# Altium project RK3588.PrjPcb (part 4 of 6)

## Sheet EMMC.SchDoc
size B; SheetNumber: 11; SheetTotal: 22
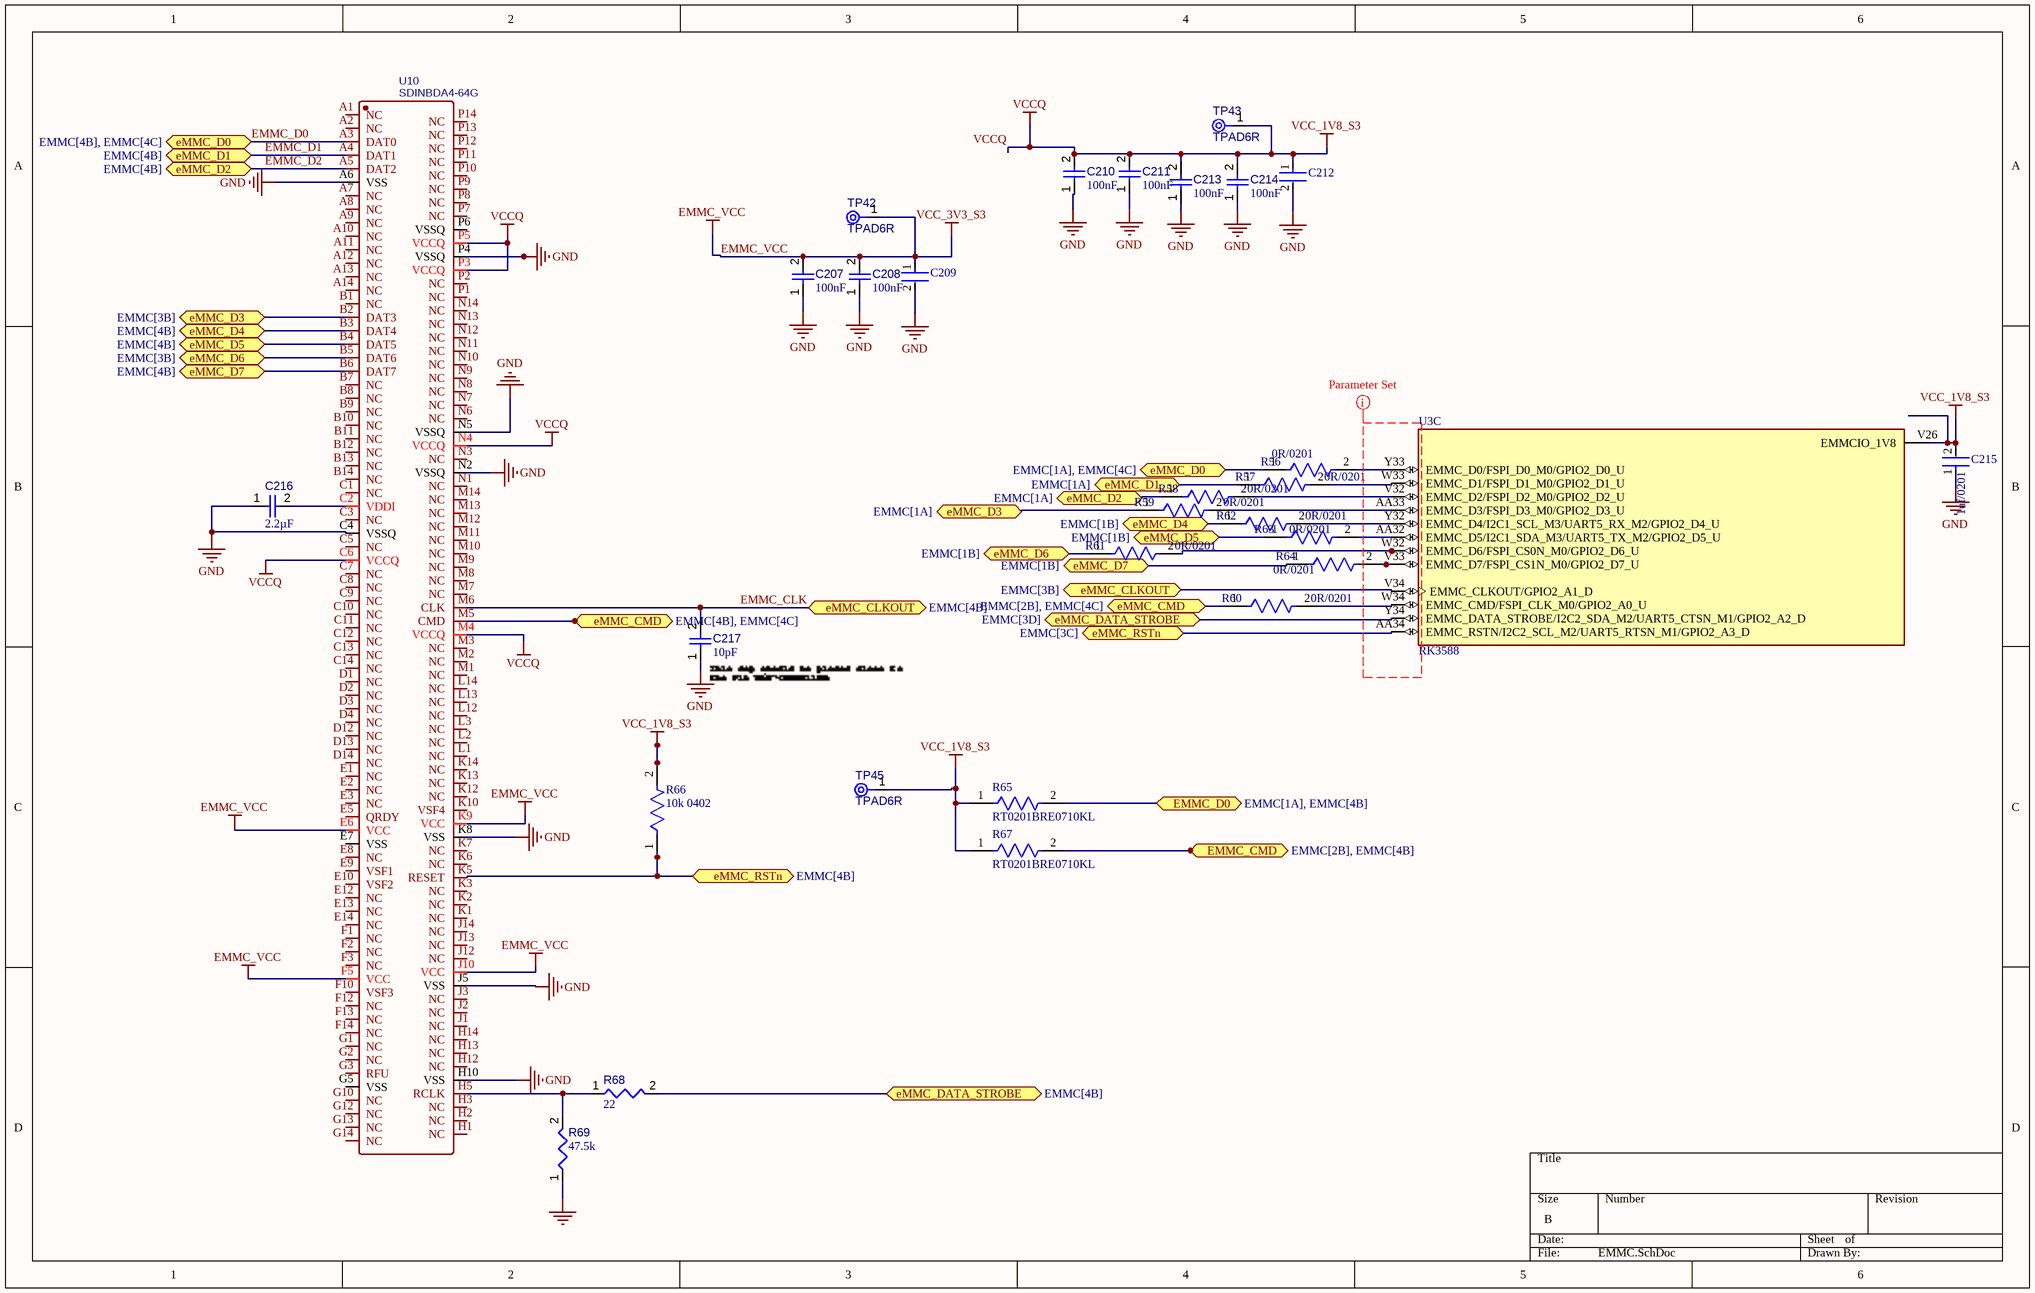
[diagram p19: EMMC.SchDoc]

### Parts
C207  value 100nF  [CAPC1005X56X25LL10T15]  (hidden comment: Capacitor 0.1 uF +/- 5% 16 V 0402)
C208  value 100nF  [CAPC1005X56X25LL10T15]  (hidden comment: Capacitor 0.1 uF +/- 5% 16 V 0402)
C209  CC0402MRX5R7BB475  [FP-CC0402-MFG]  (value not drawn)
C210  value 100nF  [CAPC1005X56X25LL10T15]  (hidden comment: Capacitor 0.1 uF +/- 5% 16 V 0402)
C211  value 100nF  [CAPC1005X56X25LL10T15]  (hidden comment: Capacitor 0.1 uF +/- 5% 16 V 0402)
C212  CC0402MRX5R7BB475  [FP-CC0402-MFG]  (value not drawn)
C213  value 100nF  [CAPC1005X56X25LL10T15]  (hidden comment: Capacitor 0.1 uF +/- 5% 16 V 0402)
C214  value 100nF  [CAPC1005X56X25LL10T15]  (hidden comment: Capacitor 0.1 uF +/- 5% 16 V 0402)
C215  1uf/0201  [FP-CC0201-BA-MFG]
C216  value 2.2µF  [CAPC0402(1005)60_L]  (hidden comment: Capacitor 2,2µF +/-20% 10V 0402)
C217  value 10pF  [CAPC1005X55X30LL05T10]  (hidden comment: Capacitor 10 pF +/- 0.25 pF 50 V 0402)
R56  0R/0201  [FP-RMCF0201-IPC_C]
R57  0R/0201  [FP-RMCF0201-IPC_C]
R58  0R/0201  [FP-RMCF0201-IPC_C]
R59  0R/0201  [FP-RMCF0201-IPC_C]
R60  0R/0201  [FP-RMCF0201-IPC_C]
R61  0R/0201  [FP-RMCF0201-IPC_C]
R62  0R/0201  [FP-RMCF0201-IPC_C]
R63  0R/0201  [FP-RMCF0201-IPC_C]
R64  0R/0201  [FP-RMCF0201-IPC_C]
R65  RT0201BRE0710KL  [FP-RT0201-MFG]
R66  10k 0402  [FP-CRGCQ0402-IPC_C]
R67  RT0201BRE0710KL  [FP-RT0201-MFG]
R68  value 22  [RESC0402(1005)_L]  (hidden comment: 22R2J)
R69  value 47.5k  [RESC0402(1005)_L]  (hidden comment: 47D5KR2F)
TP42  TPAD6R  [TP06R]  (no BOM)
TP43  TPAD6R  [TP06R]  (no BOM)
TP45  TPAD6R  [TP06R]  (no BOM)
U3  RK3588  [BGA1088C65P34X34_2300X2300X204N]  (part C of 30)
U10  SDINBDA4-64G  [FBGA-153_L13.0-W11.5-P0.50_KLMAG1JETD-B041]

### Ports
eMMC_CLKOUT (bidir, see EMMC[3B]), eMMC_CLKOUT (bidir, see EMMC[4B]), EMMC_CMD (bidir, see EMMC[2B], EMMC[4B]), eMMC_CMD (bidir, see EMMC[2B], EMMC[4C]), eMMC_CMD (bidir, see EMMC[4B], EMMC[4C]), EMMC_D0 (bidir, see EMMC[1A], EMMC[4B]), eMMC_D0 (bidir, see EMMC[1A], EMMC[4C]), eMMC_D0 (bidir, see EMMC[4B], EMMC[4C]), eMMC_D1 (bidir, see EMMC[1A]), eMMC_D1 (bidir, see EMMC[4B]), eMMC_D2 (bidir, see EMMC[1A]), eMMC_D2 (bidir, see EMMC[4B]), eMMC_D3 (bidir, see EMMC[1A]), eMMC_D3 (bidir, see EMMC[3B]), eMMC_D4 (bidir, see EMMC[1B]), eMMC_D4 (bidir, see EMMC[4B]), eMMC_D5 (bidir, see EMMC[1B]), eMMC_D5 (bidir, see EMMC[4B]), eMMC_D6 (bidir, see EMMC[1B]), eMMC_D6 (bidir, see EMMC[3B]), eMMC_D7 (bidir, see EMMC[1B]), eMMC_D7 (bidir, see EMMC[4B]), eMMC_DATA_STROBE (bidir, see EMMC[3D]), eMMC_DATA_STROBE (bidir, see EMMC[4B]), eMMC_RSTn (bidir, see EMMC[3C]), eMMC_RSTn (bidir, see EMMC[4B])

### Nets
EMMC_VCC: C207.2 C208.2 C209.1 TP42.1(TP) U10.E6(VCC) U10.F5(VCC) U10.J10(VCC) U10.K9(VCC)  [also labelled VCC_3V3_S3]
GND: C207.1 C208.1 C209.2 C210.1 C211.1 C212.2 C213.1 C214.1 C215.1 C216.1 C217.1 R69.1 U10.A6(VSS) U10.C4(VSSQ) U10.H10(VSS) U10.J5(VSS) U10.K8(VSS) U10.N2(VSSQ) U10.N5(VSSQ) U10.P4(VSSQ)
VCCQ: C210.2 C211.2 C212.1 C213.2 C214.2 C215.2 R65.1 R66.2 R67.1 TP43.1(TP) TP45.1(TP) U3.V26(EMMCIO_1V8) U10.C6(VCCQ) U10.M4(VCCQ) U10.N4(VCCQ) U10.P3(VCCQ) U10.P5(VCCQ)  [also labelled VCC_1V8_S3]
EMMC_CLK: C217.2 U3.V34(EMMC_CLKOUT/GPIO2_A1_D) U10.M6(CLK) ; port eMMC_CLKOUT
eMMC_CMD: R60.1 R67.2 U10.M5(CMD) ; port eMMC_CMD, port EMMC_CMD
EMMC_D0: R56.1 R65.2 U10.A3(DAT0) ; port eMMC_D0, port EMMC_D0
EMMC_D1: R57.1 U10.A4(DAT1) ; port eMMC_D1
EMMC_D2: R58.1 U10.A5(DAT2) ; port eMMC_D2
eMMC_D3: R59.1 U10.B2(DAT3) ; port eMMC_D3
eMMC_D4: R62.1 U10.B3(DAT4) ; port eMMC_D4
eMMC_D5: R63.1 U10.B4(DAT5) ; port eMMC_D5
eMMC_D6: R61.1 U10.B5(DAT6) ; port eMMC_D6
eMMC_D7: R64.1 U10.B6(DAT7) ; port eMMC_D7
eMMC_DATA_STROBE: R68.2 U3.Y34(EMMC_DATA_STROBE/I2C2_SDA_M2/UART5_CTSN_M1/GPIO2_A2_D) ; port eMMC_DATA_STROBE
eMMC_RSTn: R66.1 U3.AA34(EMMC_RSTN/I2C2_SCL_M2/UART5_RTSN_M1/GPIO2_A3_D) U10.K5(RESET) ; port eMMC_RSTn
NetC216_2: C216.2 U10.C2(VDDI)
NetR56_2: R56.2 U3.Y33(EMMC_D0/FSPI_D0_M0/GPIO2_D0_U)
NetR57_2: R57.2 U3.W33(EMMC_D1/FSPI_D1_M0/GPIO2_D1_U)
NetR58_2: R58.2 U3.V32(EMMC_D2/FSPI_D2_M0/GPIO2_D2_U)
NetR59_2: R59.2 U3.AA33(EMMC_D3/FSPI_D3_M0/GPIO2_D3_U)
NetR60_2: R60.2 U3.W34(EMMC_CMD/FSPI_CLK_M0/GPIO2_A0_U)
NetR61_2: R61.2 U3.W32(EMMC_D6/FSPI_CS0N_M0/GPIO2_D6_U)
NetR62_2: R62.2 U3.Y32(EMMC_D4/I2C1_SCL_M3/UART5_RX_M2/GPIO2_D4_U)
NetR63_2: R63.2 U3.AA32(EMMC_D5/I2C1_SDA_M3/UART5_TX_M2/GPIO2_D5_U)
NetR64_2: R64.2 U3.V33(EMMC_D7/FSPI_CS1N_M0/GPIO2_D7_U)
NetR68_1: R68.1 R69.2 U10.H5(RCLK)

Not connected (* = marked no-connect by the designer): U10 A1(NC) A2(NC) A7(NC) A8(NC) A9(NC) A10(NC) A11(NC) A12(NC) A13(NC) A14(NC) B1(NC) B7(NC) B8(NC) B9(NC) B10(NC) B11(NC) B12(NC) B13(NC) B14(NC) C1(NC) C3(NC) C5(NC) C7(NC) C8(NC) C9(NC) C10(NC) C11(NC) C12(NC) C13(NC) C14(NC) D1(NC) D2(NC) D3(NC) D4(NC) D12(NC) D13(NC) D14(NC) E1(NC) E2(NC) E3(NC) E5(QRDY) E7(VSS) E8(NC) E9(VSF1) E10(VSF2) E12(NC) E13(NC) E14(NC) F1(NC) F2(NC) F3(NC) F10(VSF3) F12(NC) F13(NC) F14(NC) G1(NC) G2(NC) G3(RFU) G5(VSS) G10(NC) G12(NC) G13(NC) G14(NC) H1(NC) H2(NC) H3(NC) H12(NC) H13(NC) H14(NC) J1(NC) J2(NC) J3(NC) J12(NC) J13(NC) J14(NC) K1(NC) K2(NC) K3(NC) K6(NC) K7(NC) K10(VSF4) K12(NC) K13(NC) K14(NC) L1(NC) L2(NC) L3(NC) L12(NC) L13(NC) L14(NC) M1(NC) M2(NC) M3(NC) M7(NC) M8(NC) M9(NC) M10(NC) M11(NC) M12(NC) M13(NC) M14(NC) N1(NC) N3(NC) N6(NC) N7(NC) N8(NC) N9(NC) N10(NC) N11(NC) N12(NC) N13(NC) N14(NC) P1(NC) P2(NC) P6(VSSQ) P7(NC) P8(NC) P9(NC) P10(NC) P11(NC) P12(NC) P13(NC) P14(NC)

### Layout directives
net class EMMC_50: (no net found under the mark)

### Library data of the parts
C207 C208 C210 C211 C213 C214 = CMP-001-00001-6: Chip Capacitor, 0.1 uF, +/- 5%, 16 V, 0402 (1005 Metric); Capacitor Type: Ceramic; Voltage Rating: 16V
C209 C212 = CMP-03422-000819-1: CAP CER 4.7UF 16V X5R 0402; Manufacturer: YAGEO; Tolerance: 0.2; Automotive Grade: NA; Material: Ceramic; Temperature Coefficient: 30ppm/°C
C215 = CMP-03422-000660-2: 1uF 6.3V X5R ±20% 0201 Multilayer Ceramic Capacitors MLCC - SMD/SMT ROHS; Manufacturer: Yageo; Manufacturer Part Number: CC0201MRX5R5BB105; Tolerance: 0.2; Temperature Coefficient: 15%; MN: CL03A105MQ3CSNH
C216 = CMP-001-00056-4: Chip Capacitor, 2,2µF +/-20%, 10V, 0402, Thickness 0.6 mm; Tolerance: 10%
C217 = CMP-001-00011-6: Chip Capacitor, 10 pF, +/- 0.25 pF, 50 V, 0402 (1005 Metric); Voltage Rating: 50V; Tolerance: 0.25%; Capacitor Type: Ceramic
R56-R64 = CMP-26527-001890-1: -55℃~+155℃ 0Ω 25V 50mW Thick Film Resistor 0201 Chip Resistor - Surface Mount ROHS; Resistance: 0R; MN: RMCF0201ZT0R00
R65 R67 = CMP-03412-006200-1: RT0201 10KΩ 0.05W 50 ppm/°C 0.10%; Manufacturer: Yageo; Voltage Rating: 25V; Tolerance: 0.001
R66 = CMP-03211-008081-1: CRGCQ 0402 10K 5%; Manufacturer: TE Connectivity; Manufacturer Part Number: CRGCQ0402J10K; Power Rating: 0.0625W; Tolerance: 0.05; Voltage Rating: 50V; Temperature Coefficient: ±100ppm/°C; Resistance: 10KΩ; Value: 10KΩ
R68 = CMP-009-00082-2: 22R 0.063W 5% 0402 (1005 Metric)  SMD; Power: 63mW
R69 = CMP-009-00103-2: 47K5 0.063W 1% 0402 (1005 Metric)  SMD; Power: 63mW
TP42 TP43 TP45 = CMP-00028-00002-2: 0.6mm round
U3 = RK3588: low power, high performance processor; MF: Fuzhou Rockchip Electronics Co
U10 = SDINBDA4-64G: Manufacturer: SANDISK(闪迪); Contributor: LCSC

## Sheet LPDDR4_EDA.SchDoc
size C; SheetNumber: 12; SheetTotal: 22
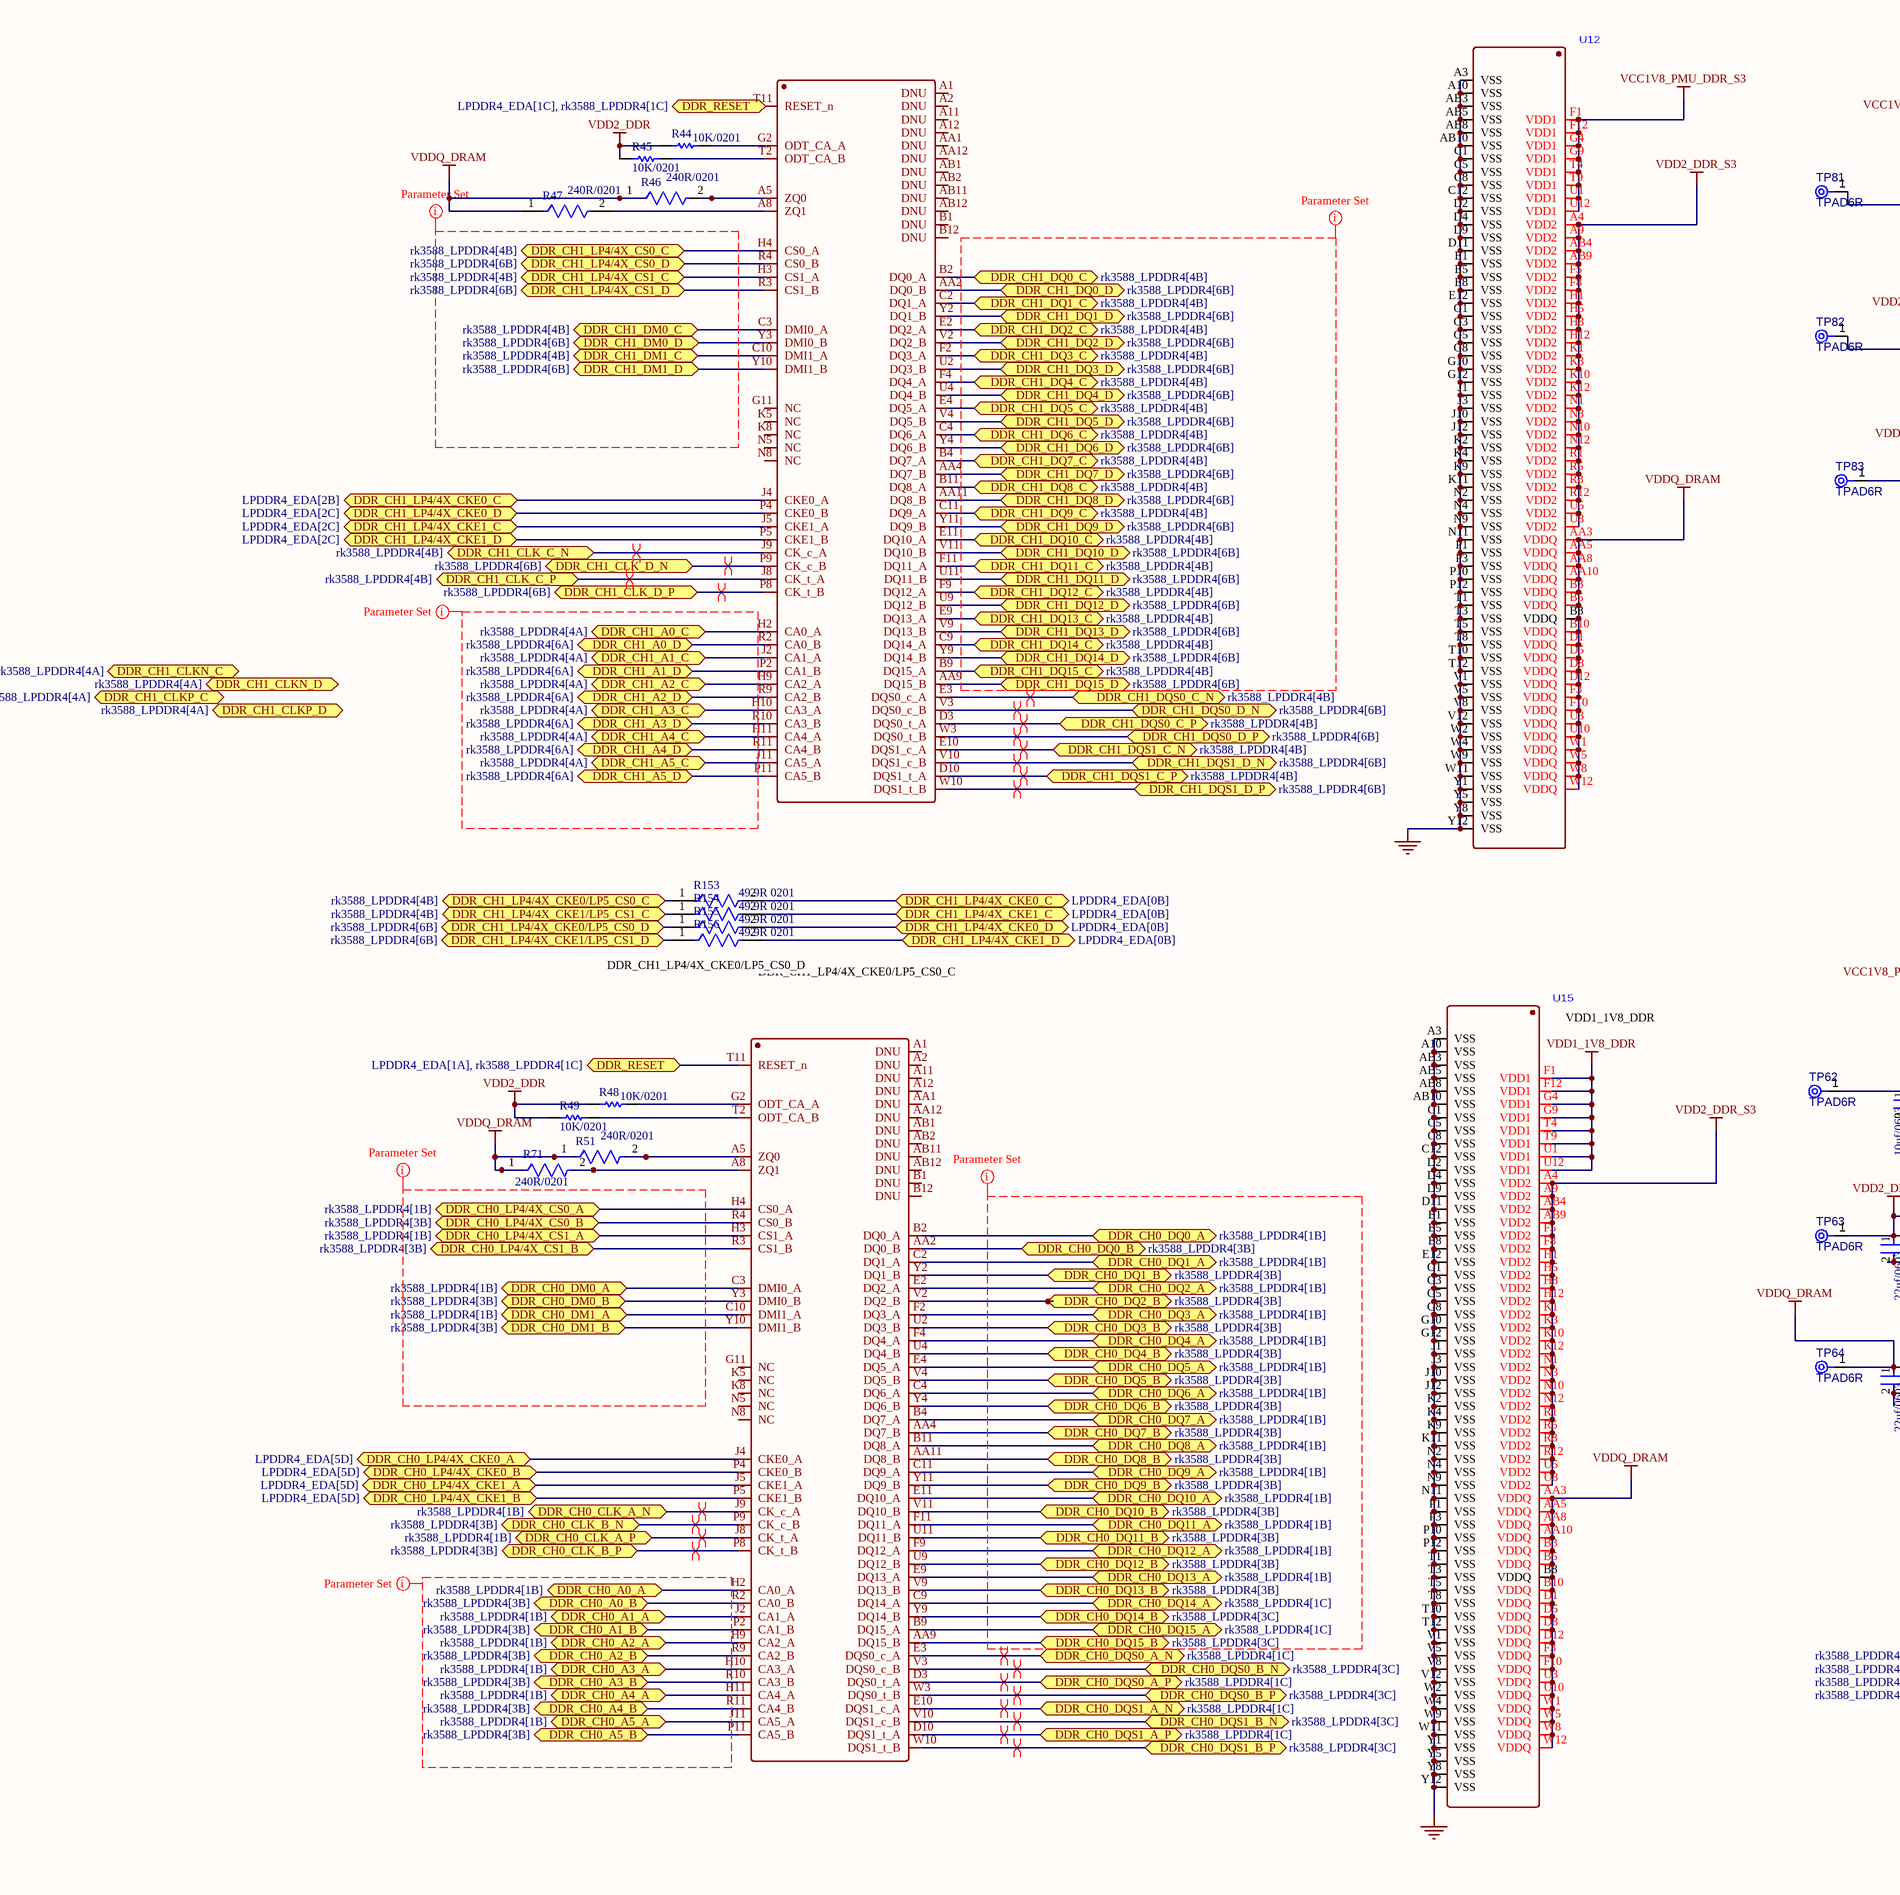
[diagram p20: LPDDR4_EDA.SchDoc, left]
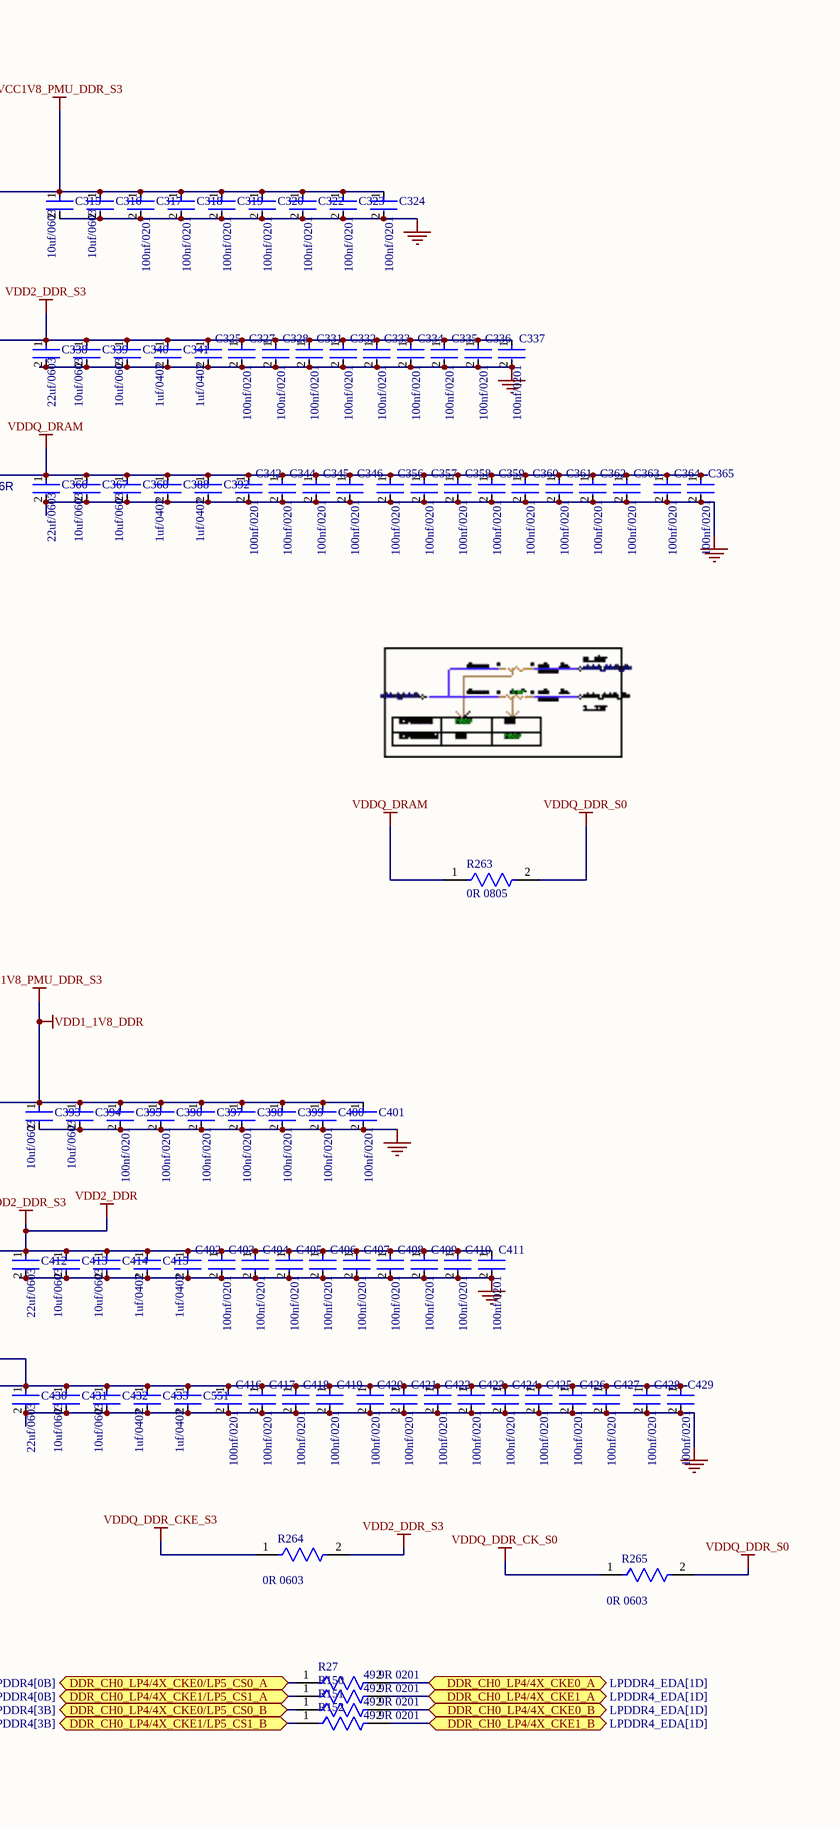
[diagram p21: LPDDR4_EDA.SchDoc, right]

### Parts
C315  10uf/0603  [FP-CC0603-DC-MFG]
C316  10uf/0603  [FP-CC0603-DC-MFG]
C317  100nf/0201  [FP-CC0201-BA-MFG]
C318  100nf/0201  [FP-CC0201-BA-MFG]
C319  100nf/0201  [FP-CC0201-BA-MFG]
C320  100nf/0201  [FP-CC0201-BA-MFG]
C322  100nf/0201  [FP-CC0201-BA-MFG]
C323  100nf/0201  [FP-CC0201-BA-MFG]
C324  100nf/0201  [FP-CC0201-BA-MFG]
C325  1uf/0402  [FP-C0402C105K8PACTU-MFG]
C327  100nf/0201  [FP-CC0201-BA-MFG]
C328  100nf/0201  [FP-CC0201-BA-MFG]
C331  100nf/0201  [FP-CC0201-BA-MFG]
C332  100nf/0201  [FP-CC0201-BA-MFG]
C333  100nf/0201  [FP-CC0201-BA-MFG]
C334  100nf/0201  [FP-CC0201-BA-MFG]
C335  100nf/0201  [FP-CC0201-BA-MFG]
C336  100nf/0201  [FP-CC0201-BA-MFG]
C337  100nf/0201  [FP-CC0201-BA-MFG]
C338  22uf/0603  [FP-GRM186-0_2-MFG]
C339  10uf/0603  [FP-CC0603-DC-MFG]
C340  10uf/0603  [FP-CC0603-DC-MFG]
C341  1uf/0402  [FP-C0402C105K8PACTU-MFG]
C342  100nf/0201  [FP-CC0201-BA-MFG]
C344  100nf/0201  [FP-CC0201-BA-MFG]
C345  100nf/0201  [FP-CC0201-BA-MFG]
C346  100nf/0201  [FP-CC0201-BA-MFG]
C356  100nf/0201  [FP-CC0201-BA-MFG]
C357  100nf/0201  [FP-CC0201-BA-MFG]
C358  100nf/0201  [FP-CC0201-BA-MFG]
C359  100nf/0201  [FP-CC0201-BA-MFG]
C360  100nf/0201  [FP-CC0201-BA-MFG]
C361  100nf/0201  [FP-CC0201-BA-MFG]
C362  100nf/0201  [FP-CC0201-BA-MFG]
C363  100nf/0201  [FP-CC0201-BA-MFG]
C364  100nf/0201  [FP-CC0201-BA-MFG]
C365  100nf/0201  [FP-CC0201-BA-MFG]
C366  22uf/0603  [FP-GRM186-0_2-MFG]
C367  10uf/0603  [FP-CC0603-DC-MFG]
C368  10uf/0603  [FP-CC0603-DC-MFG]
C388  1uf/0402  [FP-C0402C105K8PACTU-MFG]
C392  1uf/0402  [FP-C0402C105K8PACTU-MFG]
C393  10uf/0603  [FP-CC0603-DC-MFG]
C394  10uf/0603  [FP-CC0603-DC-MFG]
C395  100nf/0201  [FP-CC0201-BA-MFG]
C396  100nf/0201  [FP-CC0201-BA-MFG]
C397  100nf/0201  [FP-CC0201-BA-MFG]
C398  100nf/0201  [FP-CC0201-BA-MFG]
C399  100nf/0201  [FP-CC0201-BA-MFG]
C400  100nf/0201  [FP-CC0201-BA-MFG]
C401  100nf/0201  [FP-CC0201-BA-MFG]
C402  1uf/0402  [FP-C0402C105K8PACTU-MFG]
C403  100nf/0201  [FP-CC0201-BA-MFG]
C404  100nf/0201  [FP-CC0201-BA-MFG]
C405  100nf/0201  [FP-CC0201-BA-MFG]
C406  100nf/0201  [FP-CC0201-BA-MFG]
C407  100nf/0201  [FP-CC0201-BA-MFG]
C408  100nf/0201  [FP-CC0201-BA-MFG]
C409  100nf/0201  [FP-CC0201-BA-MFG]
C410  100nf/0201  [FP-CC0201-BA-MFG]
C411  100nf/0201  [FP-CC0201-BA-MFG]
C412  22uf/0603  [FP-GRM186-0_2-MFG]
C413  10uf/0603  [FP-CC0603-DC-MFG]
C414  10uf/0603  [FP-CC0603-DC-MFG]
C415  1uf/0402  [FP-C0402C105K8PACTU-MFG]
C416  100nf/0201  [FP-CC0201-BA-MFG]
C417  100nf/0201  [FP-CC0201-BA-MFG]
C418  100nf/0201  [FP-CC0201-BA-MFG]
C419  100nf/0201  [FP-CC0201-BA-MFG]
C420  100nf/0201  [FP-CC0201-BA-MFG]
C421  100nf/0201  [FP-CC0201-BA-MFG]
C422  100nf/0201  [FP-CC0201-BA-MFG]
C423  100nf/0201  [FP-CC0201-BA-MFG]
C424  100nf/0201  [FP-CC0201-BA-MFG]
C425  100nf/0201  [FP-CC0201-BA-MFG]
C426  100nf/0201  [FP-CC0201-BA-MFG]
C427  100nf/0201  [FP-CC0201-BA-MFG]
C428  100nf/0201  [FP-CC0201-BA-MFG]
C429  100nf/0201  [FP-CC0201-BA-MFG]
C430  22uf/0603  [FP-GRM186-0_2-MFG]
C431  10uf/0603  [FP-CC0603-DC-MFG]
C432  10uf/0603  [FP-CC0603-DC-MFG]
C433  1uf/0402  [FP-C0402C105K8PACTU-MFG]
C551  1uf/0402  [FP-C0402C105K8PACTU-MFG]
R27  49.9R 0201  [FP-AF0201-MFG]
R44  10K/0201  [RESC0603X28X15LL05T05]
R45  10K/0201  [RESC0603X28X15LL05T05]
R46  240R/0201  [FP-RMCF0201-IPC_C]
R47  240R/0201  [FP-RMCF0201-IPC_C]
R48  10K/0201  [RESC0603X28X15LL05T05]
R49  10K/0201  [RESC0603X28X15LL05T05]
R51  240R/0201  [FP-RMCF0201-IPC_C]
R71  240R/0201  [FP-RMCF0201-IPC_C]
R150  49.9R 0201  [FP-AF0201-MFG]
R151  49.9R 0201  [FP-AF0201-MFG]
R152  49.9R 0201  [FP-AF0201-MFG]
R153  49.9R 0201  [FP-AF0201-MFG]
R154  49.9R 0201  [FP-AF0201-MFG]
R155  49.9R 0201  [FP-AF0201-MFG]
R156  49.9R 0201  [FP-AF0201-MFG]
R263  0R 0805  [FP-AF0805-IPC_B]
R264  0R 0603  [FP-AC0603-IPC_C]
R265  0R 0603  [FP-AC0603-IPC_C]
TP62  TPAD6R  [TP06R]  (no BOM)
TP63  TPAD6R  [TP06R]  (no BOM)
TP64  TPAD6R  [TP06R]  (no BOM)
TP81  TPAD6R  [TP06R]  (no BOM)
TP82  TPAD6R  [TP06R]  (no BOM)
TP83  TPAD6R  [TP06R]  (no BOM)
U12  (no value)  [WFBGA-200_L14.5-W10.0-BL_MT53D512M32D2DS]
U15  (no value)  [WFBGA-200_L14.5-W10.0-BL_MT53D512M32D2DS]

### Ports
DDR_CH0_A0_A (bidir, see rk3588_LPDDR4[1B]), DDR_CH0_A0_B (bidir, see rk3588_LPDDR4[3B]), DDR_CH0_A1_A (bidir, see rk3588_LPDDR4[1B]), DDR_CH0_A1_B (bidir, see rk3588_LPDDR4[3B]), DDR_CH0_A2_A (bidir, see rk3588_LPDDR4[1B]), DDR_CH0_A2_B (bidir, see rk3588_LPDDR4[3B]), DDR_CH0_A3_A (bidir, see rk3588_LPDDR4[1B]), DDR_CH0_A3_B (bidir, see rk3588_LPDDR4[3B]), DDR_CH0_A4_A (bidir, see rk3588_LPDDR4[1B]), DDR_CH0_A4_B (bidir, see rk3588_LPDDR4[3B]), DDR_CH0_A5_A (bidir, see rk3588_LPDDR4[1B]), DDR_CH0_A5_B (bidir, see rk3588_LPDDR4[3B]), DDR_CH0_CLK_A_N (bidir, see rk3588_LPDDR4[1B]), DDR_CH0_CLK_A_P (bidir, see rk3588_LPDDR4[1B]), DDR_CH0_CLK_B_N (bidir, see rk3588_LPDDR4[3B]), DDR_CH0_CLK_B_P (bidir, see rk3588_LPDDR4[3B]), DDR_CH0_DM0_A (bidir, see rk3588_LPDDR4[1B]), DDR_CH0_DM0_B (bidir, see rk3588_LPDDR4[3B]), DDR_CH0_DM1_A (bidir, see rk3588_LPDDR4[1B]), DDR_CH0_DM1_B (bidir, see rk3588_LPDDR4[3B]), DDR_CH0_DQ0_A (bidir, see rk3588_LPDDR4[1B]), DDR_CH0_DQ0_B (bidir, see rk3588_LPDDR4[3B]), DDR_CH0_DQ1_A (bidir, see rk3588_LPDDR4[1B]), DDR_CH0_DQ1_B (bidir, see rk3588_LPDDR4[3B]), DDR_CH0_DQ2_A (bidir, see rk3588_LPDDR4[1B]), DDR_CH0_DQ2_B (bidir, see rk3588_LPDDR4[3B]), DDR_CH0_DQ3_A (bidir, see rk3588_LPDDR4[1B]), DDR_CH0_DQ3_B (bidir, see rk3588_LPDDR4[3B]), DDR_CH0_DQ4_A (bidir, see rk3588_LPDDR4[1B]), DDR_CH0_DQ4_B (bidir, see rk3588_LPDDR4[3B]), DDR_CH0_DQ5_A (bidir, see rk3588_LPDDR4[1B]), DDR_CH0_DQ5_B (bidir, see rk3588_LPDDR4[3B]), DDR_CH0_DQ6_A (bidir, see rk3588_LPDDR4[1B]), DDR_CH0_DQ6_B (bidir, see rk3588_LPDDR4[3B]), DDR_CH0_DQ7_A (bidir, see rk3588_LPDDR4[1B]), DDR_CH0_DQ7_B (bidir, see rk3588_LPDDR4[3B]), DDR_CH0_DQ8_A (bidir, see rk3588_LPDDR4[1B]), DDR_CH0_DQ8_B (bidir, see rk3588_LPDDR4[3B]), DDR_CH0_DQ9_A (bidir, see rk3588_LPDDR4[1B]), DDR_CH0_DQ9_B (bidir, see rk3588_LPDDR4[3B]), DDR_CH0_DQ10_A (bidir, see rk3588_LPDDR4[1B]), DDR_CH0_DQ10_B (bidir, see rk3588_LPDDR4[3B]), DDR_CH0_DQ11_A (bidir, see rk3588_LPDDR4[1B]), DDR_CH0_DQ11_B (bidir, see rk3588_LPDDR4[3B]), DDR_CH0_DQ12_A (bidir, see rk3588_LPDDR4[1B]), DDR_CH0_DQ12_B (bidir, see rk3588_LPDDR4[3B]), DDR_CH0_DQ13_A (bidir, see rk3588_LPDDR4[1B]), DDR_CH0_DQ13_B (bidir, see rk3588_LPDDR4[3B]), DDR_CH0_DQ14_A (bidir, see rk3588_LPDDR4[1C]), DDR_CH0_DQ14_B (bidir, see rk3588_LPDDR4[3C]), DDR_CH0_DQ15_A (bidir, see rk3588_LPDDR4[1C]), DDR_CH0_DQ15_B (bidir, see rk3588_LPDDR4[3C]), DDR_CH0_DQS0_A_N (bidir, see rk3588_LPDDR4[1C]), DDR_CH0_DQS0_A_P (bidir, see rk3588_LPDDR4[1C]), DDR_CH0_DQS0_B_N (bidir, see rk3588_LPDDR4[3C]), DDR_CH0_DQS0_B_P (bidir, see rk3588_LPDDR4[3C]), DDR_CH0_DQS1_A_N (bidir, see rk3588_LPDDR4[1C]), DDR_CH0_DQS1_A_P (bidir, see rk3588_LPDDR4[1C]), DDR_CH0_DQS1_B_N (bidir, see rk3588_LPDDR4[3C]), DDR_CH0_DQS1_B_P (bidir, see rk3588_LPDDR4[3C]), DDR_CH0_LP4/4X_CKE0/LP5_CS0_A (bidir, see rk3588_LPDDR4[0B]), DDR_CH0_LP4/4X_CKE0/LP5_CS0_B (bidir, see rk3588_LPDDR4[3B]), DDR_CH0_LP4/4X_CKE0_A (bidir, see LPDDR4_EDA[1D]), DDR_CH0_LP4/4X_CKE0_A (bidir, see LPDDR4_EDA[5D]), DDR_CH0_LP4/4X_CKE0_B (bidir, see LPDDR4_EDA[1D]), DDR_CH0_LP4/4X_CKE0_B (bidir, see LPDDR4_EDA[5D]), DDR_CH0_LP4/4X_CKE1/LP5_CS1_A (bidir, see rk3588_LPDDR4[0B]), DDR_CH0_LP4/4X_CKE1/LP5_CS1_B (bidir, see rk3588_LPDDR4[3B]), DDR_CH0_LP4/4X_CKE1_A (bidir, see LPDDR4_EDA[1D]), DDR_CH0_LP4/4X_CKE1_A (bidir, see LPDDR4_EDA[5D]), DDR_CH0_LP4/4X_CKE1_B (bidir, see LPDDR4_EDA[1D]), DDR_CH0_LP4/4X_CKE1_B (bidir, see LPDDR4_EDA[5D]), DDR_CH0_LP4/4X_CS0_A (bidir, see rk3588_LPDDR4[1B]), DDR_CH0_LP4/4X_CS0_B (bidir, see rk3588_LPDDR4[3B]), DDR_CH0_LP4/4X_CS1_A (bidir, see rk3588_LPDDR4[1B]), DDR_CH0_LP4/4X_CS1_B (bidir, see rk3588_LPDDR4[3B]), DDR_CH1_A0_C (bidir, see rk3588_LPDDR4[4A]), DDR_CH1_A0_D (bidir, see rk3588_LPDDR4[6A]), DDR_CH1_A1_C (bidir, see rk3588_LPDDR4[4A]), DDR_CH1_A1_D (bidir, see rk3588_LPDDR4[6A]), DDR_CH1_A2_C (bidir, see rk3588_LPDDR4[4A]), DDR_CH1_A2_D (bidir, see rk3588_LPDDR4[6A]), DDR_CH1_A3_C (bidir, see rk3588_LPDDR4[4A]), DDR_CH1_A3_D (bidir, see rk3588_LPDDR4[6A]), DDR_CH1_A4_C (bidir, see rk3588_LPDDR4[4A]), DDR_CH1_A4_D (bidir, see rk3588_LPDDR4[6A]), DDR_CH1_A5_C (bidir, see rk3588_LPDDR4[4A]), DDR_CH1_A5_D (bidir, see rk3588_LPDDR4[6A]), DDR_CH1_CLK_C_N (bidir, see rk3588_LPDDR4[4B]), DDR_CH1_CLK_C_P (bidir, see rk3588_LPDDR4[4B]), DDR_CH1_CLK_D_N (bidir, see rk3588_LPDDR4[6B]), DDR_CH1_CLK_D_P (bidir, see rk3588_LPDDR4[6B]), DDR_CH1_CLKN_C (bidir, see rk3588_LPDDR4[4A]), DDR_CH1_CLKN_D (bidir, see rk3588_LPDDR4[4A]), DDR_CH1_CLKP_C (bidir, see rk3588_LPDDR4[4A]), DDR_CH1_CLKP_D (bidir, see rk3588_LPDDR4[4A]), DDR_CH1_DM0_C (bidir, see rk3588_LPDDR4[4B]), DDR_CH1_DM0_D (bidir, see rk3588_LPDDR4[6B]), DDR_CH1_DM1_C (bidir, see rk3588_LPDDR4[4B]), DDR_CH1_DM1_D (bidir, see rk3588_LPDDR4[6B]), DDR_CH1_DQ0_C (bidir, see rk3588_LPDDR4[4B]), DDR_CH1_DQ0_D (bidir, see rk3588_LPDDR4[6B]), DDR_CH1_DQ1_C (bidir, see rk3588_LPDDR4[4B]), DDR_CH1_DQ1_D (bidir, see rk3588_LPDDR4[6B]), DDR_CH1_DQ2_C (bidir, see rk3588_LPDDR4[4B]), DDR_CH1_DQ2_D (bidir, see rk3588_LPDDR4[6B]), DDR_CH1_DQ3_C (bidir, see rk3588_LPDDR4[4B]), DDR_CH1_DQ3_D (bidir, see rk3588_LPDDR4[6B]), DDR_CH1_DQ4_C (bidir, see rk3588_LPDDR4[4B]), DDR_CH1_DQ4_D (bidir, see rk3588_LPDDR4[6B]), DDR_CH1_DQ5_C (bidir, see rk3588_LPDDR4[4B]), DDR_CH1_DQ5_D (bidir, see rk3588_LPDDR4[6B]), DDR_CH1_DQ6_C (bidir, see rk3588_LPDDR4[4B]), DDR_CH1_DQ6_D (bidir, see rk3588_LPDDR4[6B]), DDR_CH1_DQ7_C (bidir, see rk3588_LPDDR4[4B]), DDR_CH1_DQ7_D (bidir, see rk3588_LPDDR4[6B]), DDR_CH1_DQ8_C (bidir, see rk3588_LPDDR4[4B]), DDR_CH1_DQ8_D (bidir, see rk3588_LPDDR4[6B]), DDR_CH1_DQ9_C (bidir, see rk3588_LPDDR4[4B]), DDR_CH1_DQ9_D (bidir, see rk3588_LPDDR4[6B]), DDR_CH1_DQ10_C (bidir, see rk3588_LPDDR4[4B]), DDR_CH1_DQ10_D (bidir, see rk3588_LPDDR4[6B]), DDR_CH1_DQ11_C (bidir, see rk3588_LPDDR4[4B]), DDR_CH1_DQ11_D (bidir, see rk3588_LPDDR4[6B]), DDR_CH1_DQ12_C (bidir, see rk3588_LPDDR4[4B]), DDR_CH1_DQ12_D (bidir, see rk3588_LPDDR4[6B]), DDR_CH1_DQ13_C (bidir, see rk3588_LPDDR4[4B]), DDR_CH1_DQ13_D (bidir, see rk3588_LPDDR4[6B]), DDR_CH1_DQ14_C (bidir, see rk3588_LPDDR4[4B]), DDR_CH1_DQ14_D (bidir, see rk3588_LPDDR4[6B]), DDR_CH1_DQ15_C (bidir, see rk3588_LPDDR4[4B]), DDR_CH1_DQ15_D (bidir, see rk3588_LPDDR4[6B]), DDR_CH1_DQS0_C_N (bidir, see rk3588_LPDDR4[4B]), DDR_CH1_DQS0_C_P (bidir, see rk3588_LPDDR4[4B]), DDR_CH1_DQS0_D_N (bidir, see rk3588_LPDDR4[6B]), DDR_CH1_DQS0_D_P (bidir, see rk3588_LPDDR4[6B]), DDR_CH1_DQS1_C_N (bidir, see rk3588_LPDDR4[4B]), DDR_CH1_DQS1_C_P (bidir, see rk3588_LPDDR4[4B]), DDR_CH1_DQS1_D_N (bidir, see rk3588_LPDDR4[6B]), DDR_CH1_DQS1_D_P (bidir, see rk3588_LPDDR4[6B]), DDR_CH1_LP4/4X_CKE0/LP5_CS0_C (bidir, see rk3588_LPDDR4[4B]), DDR_CH1_LP4/4X_CKE0/LP5_CS0_D (bidir, see rk3588_LPDDR4[6B]), DDR_CH1_LP4/4X_CKE0_C (bidir, see LPDDR4_EDA[0B]), DDR_CH1_LP4/4X_CKE0_C (bidir, see LPDDR4_EDA[2B]), DDR_CH1_LP4/4X_CKE0_D (bidir, see LPDDR4_EDA[0B]), DDR_CH1_LP4/4X_CKE0_D (bidir, see LPDDR4_EDA[2C]), DDR_CH1_LP4/4X_CKE1/LP5_CS1_C (bidir, see rk3588_LPDDR4[4B]), DDR_CH1_LP4/4X_CKE1/LP5_CS1_D (bidir, see rk3588_LPDDR4[6B]), DDR_CH1_LP4/4X_CKE1_C (bidir, see LPDDR4_EDA[0B]), DDR_CH1_LP4/4X_CKE1_C (bidir, see LPDDR4_EDA[2C]), DDR_CH1_LP4/4X_CKE1_D (bidir, see LPDDR4_EDA[0B]), DDR_CH1_LP4/4X_CKE1_D (bidir, see LPDDR4_EDA[2C]), DDR_CH1_LP4/4X_CS0_C (bidir, see rk3588_LPDDR4[4B]), DDR_CH1_LP4/4X_CS0_D (bidir, see rk3588_LPDDR4[6B]), DDR_CH1_LP4/4X_CS1_C (bidir, see rk3588_LPDDR4[4B]), DDR_CH1_LP4/4X_CS1_D (bidir, see rk3588_LPDDR4[6B]), DDR_RESET (bidir, see LPDDR4_EDA[1A], rk3588_LPDDR4[1C]), DDR_RESET (bidir, see LPDDR4_EDA[1C], rk3588_LPDDR4[1C])

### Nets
GND: C315.2 C316.2 C317.2 C318.2 C319.2 C320.2 C322.2 C323.2 C324.2 C325.2 C327.2 C328.2 C331.2 C332.2 C333.2 C334.2 C335.2 C336.2 C337.2 C338.2 C339.2 C340.2 C341.2 C342.2 C344.2 C345.2 C346.2 C356.2 C357.2 C358.2 C359.2 C360.2 C361.2 C362.2 C363.2 C364.2 C365.2 C366.2 C367.2 C368.2 C388.2 C392.2 C393.2 C394.2 C395.2 C396.2 C397.2 C398.2 C399.2 C400.2 C401.2 C402.2 C403.2 C404.2 C405.2 C406.2 C407.2 C408.2 C409.2 C410.2 C411.2 C412.2 C413.2 C414.2 C415.2 C416.2 C417.2 C418.2 C419.2 C420.2 C421.2 C422.2 C423.2 C424.2 C425.2 C426.2 C427.2 C428.2 C429.2 C430.2 C431.2 C432.2 C433.2 C551.2 U12.A3(VSS) U12.A10(VSS) U12.AB3(VSS) U12.AB5(VSS) U12.AB8(VSS) U12.AB10(VSS) U12.C1(VSS) U12.C5(VSS) U12.C8(VSS) U12.C12(VSS) U12.D2(VSS) U12.D4(VSS) U12.D9(VSS) U12.D11(VSS) U12.E1(VSS) U12.E5(VSS) U12.E8(VSS) U12.E12(VSS) U12.G1(VSS) U12.G3(VSS) U12.G5(VSS) U12.G8(VSS) U12.G10(VSS) U12.G12(VSS) U12.J1(VSS) U12.J3(VSS) U12.J10(VSS) U12.J12(VSS) U12.K2(VSS) U12.K4(VSS) U12.K9(VSS) U12.K11(VSS) U12.N2(VSS) U12.N4(VSS) U12.N9(VSS) U12.N11(VSS) U12.P1(VSS) U12.P3(VSS) U12.P10(VSS) U12.P12(VSS) U12.T1(VSS) U12.T3(VSS) U12.T5(VSS) U12.T8(VSS) U12.T10(VSS) U12.T12(VSS) U12.V1(VSS) U12.V5(VSS) U12.V8(VSS) U12.V12(VSS) U12.W2(VSS) U12.W4(VSS) U12.W9(VSS) U12.W11(VSS) U12.Y1(VSS) U12.Y5(VSS) U12.Y8(VSS) U12.Y12(VSS) U15.A3(VSS) U15.A10(VSS) U15.AB3(VSS) U15.AB5(VSS) U15.AB8(VSS) U15.AB10(VSS) U15.C1(VSS) U15.C5(VSS) U15.C8(VSS) U15.C12(VSS) U15.D2(VSS) U15.D4(VSS) U15.D9(VSS) U15.D11(VSS) U15.E1(VSS) U15.E5(VSS) U15.E8(VSS) U15.E12(VSS) U15.G1(VSS) U15.G3(VSS) U15.G5(VSS) U15.G8(VSS) U15.G10(VSS) U15.G12(VSS) U15.J1(VSS) U15.J3(VSS) U15.J10(VSS) U15.J12(VSS) U15.K2(VSS) U15.K4(VSS) U15.K9(VSS) U15.K11(VSS) U15.N2(VSS) U15.N4(VSS) U15.N9(VSS) U15.N11(VSS) U15.P1(VSS) U15.P3(VSS) U15.P10(VSS) U15.P12(VSS) U15.T1(VSS) U15.T3(VSS) U15.T5(VSS) U15.T8(VSS) U15.T10(VSS) U15.T12(VSS) U15.V1(VSS) U15.V5(VSS) U15.V8(VSS) U15.V12(VSS) U15.W2(VSS) U15.W4(VSS) U15.W9(VSS) U15.W11(VSS) U15.Y1(VSS) U15.Y5(VSS) U15.Y8(VSS) U15.Y12(VSS)
VCC1V8_PMU_DDR_S3: C315.1 C316.1 C317.1 C318.1 C319.1 C320.1 C322.1 C323.1 C324.1 C393.1 C394.1 C395.1 C396.1 C397.1 C398.1 C399.1 C400.1 C401.1 TP62.1(TP) TP81.1(TP) U12.F1(VDD1) U12.F12(VDD1) U12.G4(VDD1) U12.G9(VDD1) U12.T4(VDD1) U12.T9(VDD1) U12.U1(VDD1) U12.U12(VDD1) U15.F1(VDD1) U15.F12(VDD1) U15.G4(VDD1) U15.G9(VDD1) U15.T4(VDD1) U15.T9(VDD1) U15.U1(VDD1) U15.U12(VDD1)  [also labelled VDD1_1V8_DDR]
VDD2_DDR: C325.1 C327.1 C328.1 C331.1 C332.1 C333.1 C334.1 C335.1 C336.1 C337.1 C338.1 C339.1 C340.1 C341.1 C402.1 C403.1 C404.1 C405.1 C406.1 C407.1 C408.1 C409.1 C410.1 C411.1 C412.1 C413.1 C414.1 C415.1 R44.1 R45.1 R48.1 R49.1 R264.2 TP63.1(TP) TP82.1(TP) U12.A4(VDD2) U12.A9(VDD2) U12.AB4(VDD2) U12.AB9(VDD2) U12.F5(VDD2) U12.F8(VDD2) U12.H1(VDD2) U12.H5(VDD2) U12.H8(VDD2) U12.H12(VDD2) U12.K1(VDD2) U12.K3(VDD2) U12.K10(VDD2) U12.K12(VDD2) U12.N1(VDD2) U12.N3(VDD2) U12.N10(VDD2) U12.N12(VDD2) U12.R1(VDD2) U12.R5(VDD2) U12.R8(VDD2) U12.R12(VDD2) U12.U5(VDD2) U12.U8(VDD2) U15.A4(VDD2) U15.A9(VDD2) U15.AB4(VDD2) U15.AB9(VDD2) U15.F5(VDD2) U15.F8(VDD2) U15.H1(VDD2) U15.H5(VDD2) U15.H8(VDD2) U15.H12(VDD2) U15.K1(VDD2) U15.K3(VDD2) U15.K10(VDD2) U15.K12(VDD2) U15.N1(VDD2) U15.N3(VDD2) U15.N10(VDD2) U15.N12(VDD2) U15.R1(VDD2) U15.R5(VDD2) U15.R8(VDD2) U15.R12(VDD2) U15.U5(VDD2) U15.U8(VDD2)  [also labelled VDD2_DDR_S3]  [project net VOUT6]
VDDQ_DDR_CK_S0: R265.1  [project net VDDQ_DDR_CK]
VDDQ_DDR_CKE_S3: R264.1  [project net VDD2_DDR_CKE]
VDDQ_DDR_S0: R263.2 R265.2  [project net VOUT9]
VDDQ_DRAM: C342.1 C344.1 C345.1 C346.1 C356.1 C357.1 C358.1 C359.1 C360.1 C361.1 C362.1 C363.1 C364.1 C365.1 C366.1 C367.1 C368.1 C388.1 C392.1 C416.1 C417.1 C418.1 C419.1 C420.1 C421.1 C422.1 C423.1 C424.1 C425.1 C426.1 C427.1 C428.1 C429.1 C430.1 C431.1 C432.1 C433.1 C551.1 R46.1 R47.1 R51.1 R71.1 R263.1 TP64.1(TP) TP83.1(TP) U12.AA3(VDDQ) U12.AA5(VDDQ) U12.AA8(VDDQ) U12.AA10(VDDQ) U12.B3(VDDQ) U12.B5(VDDQ) U12.B8(VDDQ) U12.B10(VDDQ) U12.D1(VDDQ) U12.D5(VDDQ) U12.D8(VDDQ) U12.D12(VDDQ) U12.F3(VDDQ) U12.F10(VDDQ) U12.U3(VDDQ) U12.U10(VDDQ) U12.W1(VDDQ) U12.W5(VDDQ) U12.W8(VDDQ) U12.W12(VDDQ) U15.AA3(VDDQ) U15.AA5(VDDQ) U15.AA8(VDDQ) U15.AA10(VDDQ) U15.B3(VDDQ) U15.B5(VDDQ) U15.B8(VDDQ) U15.B10(VDDQ) U15.D1(VDDQ) U15.D5(VDDQ) U15.D8(VDDQ) U15.D12(VDDQ) U15.F3(VDDQ) U15.F10(VDDQ) U15.U3(VDDQ) U15.U10(VDDQ) U15.W1(VDDQ) U15.W5(VDDQ) U15.W8(VDDQ) U15.W12(VDDQ)
DDR_CH0_A0_A: U15.H2(CA0_A) ; port DDR_CH0_A0_A
DDR_CH0_A0_B: U15.R2(CA0_B) ; port DDR_CH0_A0_B
DDR_CH0_A1_A: U15.J2(CA1_A) ; port DDR_CH0_A1_A
DDR_CH0_A1_B: U15.P2(CA1_B) ; port DDR_CH0_A1_B
DDR_CH0_A2_A: U15.H9(CA2_A) ; port DDR_CH0_A2_A
DDR_CH0_A2_B: U15.R9(CA2_B) ; port DDR_CH0_A2_B
DDR_CH0_A3_A: U15.H10(CA3_A) ; port DDR_CH0_A3_A
DDR_CH0_A3_B: U15.R10(CA3_B) ; port DDR_CH0_A3_B
DDR_CH0_A4_A: U15.H11(CA4_A) ; port DDR_CH0_A4_A
DDR_CH0_A4_B: U15.R11(CA4_B) ; port DDR_CH0_A4_B
DDR_CH0_A5_A: U15.J11(CA5_A) ; port DDR_CH0_A5_A
DDR_CH0_A5_B: U15.P11(CA5_B) ; port DDR_CH0_A5_B
DDR_CH0_CLK_A_N: U15.J9(CK_c_A) ; port DDR_CH0_CLK_A_N
DDR_CH0_CLK_A_P: U15.J8(CK_t_A) ; port DDR_CH0_CLK_A_P
DDR_CH0_CLK_B_N: U15.P9(CK_c_B) ; port DDR_CH0_CLK_B_N
DDR_CH0_CLK_B_P: U15.P8(CK_t_B) ; port DDR_CH0_CLK_B_P
DDR_CH0_DM0_A: U15.C3(DMI0_A) ; port DDR_CH0_DM0_A
DDR_CH0_DM0_B: U15.Y3(DMI0_B) ; port DDR_CH0_DM0_B
DDR_CH0_DM1_A: U15.C10(DMI1_A) ; port DDR_CH0_DM1_A
DDR_CH0_DM1_B: U15.Y10(DMI1_B) ; port DDR_CH0_DM1_B
DDR_CH0_DQ0_A: U15.B2(DQ0_A) ; port DDR_CH0_DQ0_A
DDR_CH0_DQ0_B: U15.AA2(DQ0_B) ; port DDR_CH0_DQ0_B
DDR_CH0_DQ1_A: U15.C2(DQ1_A) ; port DDR_CH0_DQ1_A
DDR_CH0_DQ1_B: U15.Y2(DQ1_B) ; port DDR_CH0_DQ1_B
DDR_CH0_DQ2_A: U15.E2(DQ2_A) ; port DDR_CH0_DQ2_A
DDR_CH0_DQ2_B: U15.V2(DQ2_B) ; port DDR_CH0_DQ2_B
DDR_CH0_DQ3_A: U15.F2(DQ3_A) ; port DDR_CH0_DQ3_A
DDR_CH0_DQ3_B: U15.U2(DQ3_B) ; port DDR_CH0_DQ3_B
DDR_CH0_DQ4_A: U15.F4(DQ4_A) ; port DDR_CH0_DQ4_A
DDR_CH0_DQ4_B: U15.U4(DQ4_B) ; port DDR_CH0_DQ4_B
DDR_CH0_DQ5_A: U15.E4(DQ5_A) ; port DDR_CH0_DQ5_A
DDR_CH0_DQ5_B: U15.V4(DQ5_B) ; port DDR_CH0_DQ5_B
DDR_CH0_DQ6_A: U15.C4(DQ6_A) ; port DDR_CH0_DQ6_A
DDR_CH0_DQ6_B: U15.Y4(DQ6_B) ; port DDR_CH0_DQ6_B
DDR_CH0_DQ7_A: U15.B4(DQ7_A) ; port DDR_CH0_DQ7_A
DDR_CH0_DQ7_B: U15.AA4(DQ7_B) ; port DDR_CH0_DQ7_B
DDR_CH0_DQ8_A: U15.B11(DQ8_A) ; port DDR_CH0_DQ8_A
DDR_CH0_DQ8_B: U15.AA11(DQ8_B) ; port DDR_CH0_DQ8_B
DDR_CH0_DQ9_A: U15.C11(DQ9_A) ; port DDR_CH0_DQ9_A
DDR_CH0_DQ9_B: U15.Y11(DQ9_B) ; port DDR_CH0_DQ9_B
DDR_CH0_DQ10_A: U15.E11(DQ10_A) ; port DDR_CH0_DQ10_A
DDR_CH0_DQ10_B: U15.V11(DQ10_B) ; port DDR_CH0_DQ10_B
DDR_CH0_DQ11_A: U15.F11(DQ11_A) ; port DDR_CH0_DQ11_A
DDR_CH0_DQ11_B: U15.U11(DQ11_B) ; port DDR_CH0_DQ11_B
DDR_CH0_DQ12_A: U15.F9(DQ12_A) ; port DDR_CH0_DQ12_A
DDR_CH0_DQ12_B: U15.U9(DQ12_B) ; port DDR_CH0_DQ12_B
DDR_CH0_DQ13_A: U15.E9(DQ13_A) ; port DDR_CH0_DQ13_A
DDR_CH0_DQ13_B: U15.V9(DQ13_B) ; port DDR_CH0_DQ13_B
DDR_CH0_DQ14_A: U15.C9(DQ14_A) ; port DDR_CH0_DQ14_A
DDR_CH0_DQ14_B: U15.Y9(DQ14_B) ; port DDR_CH0_DQ14_B
DDR_CH0_DQ15_A: U15.B9(DQ15_A) ; port DDR_CH0_DQ15_A
DDR_CH0_DQ15_B: U15.AA9(DQ15_B) ; port DDR_CH0_DQ15_B
DDR_CH0_DQS0_A_N: U15.E3(DQS0_c_A) ; port DDR_CH0_DQS0_A_N
DDR_CH0_DQS0_A_P: U15.D3(DQS0_t_A) ; port DDR_CH0_DQS0_A_P
DDR_CH0_DQS0_B_N: U15.V3(DQS0_c_B) ; port DDR_CH0_DQS0_B_N
DDR_CH0_DQS0_B_P: U15.W3(DQS0_t_B) ; port DDR_CH0_DQS0_B_P
DDR_CH0_DQS1_A_N: U15.E10(DQS1_c_A) ; port DDR_CH0_DQS1_A_N
DDR_CH0_DQS1_A_P: U15.D10(DQS1_t_A) ; port DDR_CH0_DQS1_A_P
DDR_CH0_DQS1_B_N: U15.V10(DQS1_c_B) ; port DDR_CH0_DQS1_B_N
DDR_CH0_DQS1_B_P: U15.W10(DQS1_t_B) ; port DDR_CH0_DQS1_B_P
DDR_CH0_LP4/4X_CKE0/LP5_CS0_A: R27.1 ; port DDR_CH0_LP4/4X_CKE0/LP5_CS0_A
DDR_CH0_LP4/4X_CKE0/LP5_CS0_B: R151.1 ; port DDR_CH0_LP4/4X_CKE0/LP5_CS0_B
DDR_CH0_LP4/4X_CKE0_A: R27.2 U15.J4(CKE0_A) ; port DDR_CH0_LP4/4X_CKE0_A
DDR_CH0_LP4/4X_CKE0_B: R151.2 U15.P4(CKE0_B) ; port DDR_CH0_LP4/4X_CKE0_B
DDR_CH0_LP4/4X_CKE1/LP5_CS1_A: R150.1 ; port DDR_CH0_LP4/4X_CKE1/LP5_CS1_A
DDR_CH0_LP4/4X_CKE1/LP5_CS1_B: R152.1 ; port DDR_CH0_LP4/4X_CKE1/LP5_CS1_B
DDR_CH0_LP4/4X_CKE1_A: R150.2 U15.J5(CKE1_A) ; port DDR_CH0_LP4/4X_CKE1_A
DDR_CH0_LP4/4X_CKE1_B: R152.2 U15.P5(CKE1_B) ; port DDR_CH0_LP4/4X_CKE1_B
DDR_CH0_LP4/4X_CS0_A: U15.H4(CS0_A) ; port DDR_CH0_LP4/4X_CS0_A
DDR_CH0_LP4/4X_CS0_B: U15.R4(CS0_B) ; port DDR_CH0_LP4/4X_CS0_B
DDR_CH0_LP4/4X_CS1_A: U15.H3(CS1_A) ; port DDR_CH0_LP4/4X_CS1_A
DDR_CH0_LP4/4X_CS1_B: U15.R3(CS1_B) ; port DDR_CH0_LP4/4X_CS1_B
DDR_CH1_A0_C: U12.H2(CA0_A) ; port DDR_CH1_A0_C
DDR_CH1_A0_D: U12.R2(CA0_B) ; port DDR_CH1_A0_D
DDR_CH1_A1_C: U12.J2(CA1_A) ; port DDR_CH1_A1_C
DDR_CH1_A1_D: U12.P2(CA1_B) ; port DDR_CH1_A1_D
DDR_CH1_A2_C: U12.H9(CA2_A) ; port DDR_CH1_A2_C
DDR_CH1_A2_D: U12.R9(CA2_B) ; port DDR_CH1_A2_D
DDR_CH1_A3_C: U12.H10(CA3_A) ; port DDR_CH1_A3_C
DDR_CH1_A3_D: U12.R10(CA3_B) ; port DDR_CH1_A3_D
DDR_CH1_A4_C: U12.H11(CA4_A) ; port DDR_CH1_A4_C
DDR_CH1_A4_D: U12.R11(CA4_B) ; port DDR_CH1_A4_D
DDR_CH1_A5_C: U12.J11(CA5_A) ; port DDR_CH1_A5_C
DDR_CH1_A5_D: U12.P11(CA5_B) ; port DDR_CH1_A5_D
DDR_CH1_CLK_C_N: U12.J9(CK_c_A) ; port DDR_CH1_CLK_C_N
DDR_CH1_CLK_C_P: U12.J8(CK_t_A) ; port DDR_CH1_CLK_C_P
DDR_CH1_CLK_D_N: U12.P9(CK_c_B) ; port DDR_CH1_CLK_D_N
DDR_CH1_CLK_D_P: U12.P8(CK_t_B) ; port DDR_CH1_CLK_D_P
DDR_CH1_DM0_C: U12.C3(DMI0_A) ; port DDR_CH1_DM0_C
DDR_CH1_DM0_D: U12.Y3(DMI0_B) ; port DDR_CH1_DM0_D
DDR_CH1_DM1_C: U12.C10(DMI1_A) ; port DDR_CH1_DM1_C
DDR_CH1_DM1_D: U12.Y10(DMI1_B) ; port DDR_CH1_DM1_D
DDR_CH1_DQ0_C: U12.B2(DQ0_A) ; port DDR_CH1_DQ0_C
DDR_CH1_DQ0_D: U12.AA2(DQ0_B) ; port DDR_CH1_DQ0_D
DDR_CH1_DQ1_C: U12.C2(DQ1_A) ; port DDR_CH1_DQ1_C
DDR_CH1_DQ1_D: U12.Y2(DQ1_B) ; port DDR_CH1_DQ1_D
DDR_CH1_DQ2_C: U12.E2(DQ2_A) ; port DDR_CH1_DQ2_C
DDR_CH1_DQ2_D: U12.V2(DQ2_B) ; port DDR_CH1_DQ2_D
DDR_CH1_DQ3_C: U12.F2(DQ3_A) ; port DDR_CH1_DQ3_C
DDR_CH1_DQ3_D: U12.U2(DQ3_B) ; port DDR_CH1_DQ3_D
DDR_CH1_DQ4_C: U12.F4(DQ4_A) ; port DDR_CH1_DQ4_C
DDR_CH1_DQ4_D: U12.U4(DQ4_B) ; port DDR_CH1_DQ4_D
DDR_CH1_DQ5_C: U12.E4(DQ5_A) ; port DDR_CH1_DQ5_C
DDR_CH1_DQ5_D: U12.V4(DQ5_B) ; port DDR_CH1_DQ5_D
DDR_CH1_DQ6_C: U12.C4(DQ6_A) ; port DDR_CH1_DQ6_C
DDR_CH1_DQ6_D: U12.Y4(DQ6_B) ; port DDR_CH1_DQ6_D
DDR_CH1_DQ7_C: U12.B4(DQ7_A) ; port DDR_CH1_DQ7_C
DDR_CH1_DQ7_D: U12.AA4(DQ7_B) ; port DDR_CH1_DQ7_D
DDR_CH1_DQ8_C: U12.B11(DQ8_A) ; port DDR_CH1_DQ8_C
DDR_CH1_DQ8_D: U12.AA11(DQ8_B) ; port DDR_CH1_DQ8_D
DDR_CH1_DQ9_C: U12.C11(DQ9_A) ; port DDR_CH1_DQ9_C
DDR_CH1_DQ9_D: U12.Y11(DQ9_B) ; port DDR_CH1_DQ9_D
DDR_CH1_DQ10_C: U12.E11(DQ10_A) ; port DDR_CH1_DQ10_C
DDR_CH1_DQ10_D: U12.V11(DQ10_B) ; port DDR_CH1_DQ10_D
DDR_CH1_DQ11_C: U12.F11(DQ11_A) ; port DDR_CH1_DQ11_C
DDR_CH1_DQ11_D: U12.U11(DQ11_B) ; port DDR_CH1_DQ11_D
DDR_CH1_DQ12_C: U12.F9(DQ12_A) ; port DDR_CH1_DQ12_C
DDR_CH1_DQ12_D: U12.U9(DQ12_B) ; port DDR_CH1_DQ12_D
DDR_CH1_DQ13_C: U12.E9(DQ13_A) ; port DDR_CH1_DQ13_C
DDR_CH1_DQ13_D: U12.V9(DQ13_B) ; port DDR_CH1_DQ13_D
DDR_CH1_DQ14_C: U12.C9(DQ14_A) ; port DDR_CH1_DQ14_C
DDR_CH1_DQ14_D: U12.Y9(DQ14_B) ; port DDR_CH1_DQ14_D
DDR_CH1_DQ15_C: U12.B9(DQ15_A) ; port DDR_CH1_DQ15_C
DDR_CH1_DQ15_D: U12.AA9(DQ15_B) ; port DDR_CH1_DQ15_D
DDR_CH1_DQS0_C_N: U12.E3(DQS0_c_A) ; port DDR_CH1_DQS0_C_N
DDR_CH1_DQS0_C_P: U12.D3(DQS0_t_A) ; port DDR_CH1_DQS0_C_P
DDR_CH1_DQS0_D_N: U12.V3(DQS0_c_B) ; port DDR_CH1_DQS0_D_N
DDR_CH1_DQS0_D_P: U12.W3(DQS0_t_B) ; port DDR_CH1_DQS0_D_P
DDR_CH1_DQS1_C_N: U12.E10(DQS1_c_A) ; port DDR_CH1_DQS1_C_N
DDR_CH1_DQS1_C_P: U12.D10(DQS1_t_A) ; port DDR_CH1_DQS1_C_P
DDR_CH1_DQS1_D_N: U12.V10(DQS1_c_B) ; port DDR_CH1_DQS1_D_N
DDR_CH1_DQS1_D_P: U12.W10(DQS1_t_B) ; port DDR_CH1_DQS1_D_P
DDR_CH1_LP4/4X_CKE0/LP5_CS0_C: R153.1 ; port DDR_CH1_LP4/4X_CKE0/LP5_CS0_C
DDR_CH1_LP4/4X_CKE0/LP5_CS0_D: R155.1 ; port DDR_CH1_LP4/4X_CKE0/LP5_CS0_D
DDR_CH1_LP4/4X_CKE0_C: R153.2 U12.J4(CKE0_A) ; port DDR_CH1_LP4/4X_CKE0_C
DDR_CH1_LP4/4X_CKE0_D: R155.2 U12.P4(CKE0_B) ; port DDR_CH1_LP4/4X_CKE0_D
DDR_CH1_LP4/4X_CKE1/LP5_CS1_C: R154.1 ; port DDR_CH1_LP4/4X_CKE1/LP5_CS1_C
DDR_CH1_LP4/4X_CKE1/LP5_CS1_D: R156.1 ; port DDR_CH1_LP4/4X_CKE1/LP5_CS1_D
DDR_CH1_LP4/4X_CKE1_C: R154.2 U12.J5(CKE1_A) ; port DDR_CH1_LP4/4X_CKE1_C
DDR_CH1_LP4/4X_CKE1_D: R156.2 U12.P5(CKE1_B) ; port DDR_CH1_LP4/4X_CKE1_D
DDR_CH1_LP4/4X_CS0_C: U12.H4(CS0_A) ; port DDR_CH1_LP4/4X_CS0_C
DDR_CH1_LP4/4X_CS0_D: U12.R4(CS0_B) ; port DDR_CH1_LP4/4X_CS0_D
DDR_CH1_LP4/4X_CS1_C: U12.H3(CS1_A) ; port DDR_CH1_LP4/4X_CS1_C
DDR_CH1_LP4/4X_CS1_D: U12.R3(CS1_B) ; port DDR_CH1_LP4/4X_CS1_D
DDR_RESET: U15.T11(RESET_n) ; port DDR_RESET
NetR44_2: R44.2 U12.G2(ODT_CA_A)
NetR45_2: R45.2 U12.T2(ODT_CA_B)
NetR46_2: R46.2 U12.A5(ZQ0)
NetR47_2: R47.2 U12.A8(ZQ1)
NetR48_2: R48.2 U15.G2(ODT_CA_A)
NetR49_2: R49.2 U15.T2(ODT_CA_B)
NetR51_2: R51.2 U15.A5(ZQ0)
NetR71_2: R71.2 U15.A8(ZQ1)

Not connected (* = marked no-connect by the designer): U12 A1(DNU) A2(DNU) A11(DNU) A12(DNU) AA1(DNU) AA12(DNU) AB1(DNU) AB2(DNU) AB11(DNU) AB12(DNU) B1(DNU) B12(DNU) G11(NC) K5(NC) K8(NC) N5(NC) N8(NC) T11(RESET_n); U15 A1(DNU) A2(DNU) A11(DNU) A12(DNU) AA1(DNU) AA12(DNU) AB1(DNU) AB2(DNU) AB11(DNU) AB12(DNU) B1(DNU) B12(DNU) G11(NC) K5(NC) K8(NC) N5(NC) N8(NC)

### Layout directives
net class DRAM_2: (no net found under the mark)
net class DRAM_1: (no net found under the mark)
differential pair; differential pair class RAM_80: DDR_CH0_CLK_A_N, DDR_CH0_CLK_A_P, DDR_CH0_CLK_B_N, DDR_CH0_CLK_B_P, DDR_CH0_DQS0_A_N, DDR_CH0_DQS0_A_P, DDR_CH0_DQS0_B_N, DDR_CH0_DQS0_B_P, DDR_CH0_DQS1_A_N, DDR_CH0_DQS1_A_P, DDR_CH0_DQS1_B_N, DDR_CH0_DQS1_B_P, DDR_CH1_CLK_C_N, DDR_CH1_CLK_C_P, DDR_CH1_CLK_D_N, DDR_CH1_CLK_D_P, DDR_CH1_DQS0_C_N, DDR_CH1_DQS0_C_P, DDR_CH1_DQS0_D_N, DDR_CH1_DQS0_D_P, DDR_CH1_DQS1_C_N, DDR_CH1_DQS1_C_P, DDR_CH1_DQS1_D_N, DDR_CH1_DQS1_D_P

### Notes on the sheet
- (near R156) DDR_CH1_LP4/4X_CKE0/LP5_CS0_D
- DDR_CH1_LP4/4X_CKE0/LP5_CS0_C
- (near U15) VDD1_1V8_DDR

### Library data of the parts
C315 C316 C339 C340 C367 C368 C393 C394 C413 C414 C431 C432 = CMP-00621-81932632-1: CC0603KRX5R7BB106 Multilayer Ceramic Capacitor, 10 uF, 16 V, ± 10%, X5R, 0603 [1608 Metric]; Capacitance: 10µF; Voltage Rating: 16V
C317-C320 C322-C324 C327 C328 C331-C337 C342 C344-C346 C356-C365 C395-C401 C403-C411 C416-C429 = CMP-03422-000955-1: CC0201 100 nF X5R 20.00% 10 V; Manufacturer: Yageo; Manufacturer Part Number: CC0201MRX5R6BB104; Tolerance: 0.2; Temperature Coefficient: 15%; Capacitance: 100 nF; Voltage Rating: 10 V; Value: 100 nF; Material: Ceramic
C325 C341 C388 C392 C402 C415 C433 C551 = CMP-2008-02081-2: CAP CER 1UF 10V X5R 0402; Dielectric Material: Ceramic; Dissipation Factor: 5%; Tolerance: 10%
C338 C366 C412 C430 = CMP-06035-006914-1: Chip Multilayer Ceramic Capacitors for General Purpose, 0603, 22uF, X5R, 15%, 20%, 6.3V
R27 R150-R156 = CMP-03412-044155-1: Anti-Sulfurated Chip Resistors Automotive Grade 49.9Ω 1% 200ppm/°C 0201; Max Power Dissipation: 50mW
R44 R45 R48 R49 = CMP-2004-00015-1: Part Number: CRCW020110K0FKED; Manufacturer: Vishay Dale
R46 R47 R51 R71 = CMP-26527-006303-1: 240Ω ±1% 0.05W 0201 Thick Film Chip Resistor AEC-Q200 compliant; Temperature Coefficient: 200ppm/°C; Resistance: 240R; Max Power Dissipation: 50mW
R263 = CMP-03412-047152-1: Anti-Sulfurated Chip Resistor Automotive Grade 0Ω Jumper 0.125W 0805; Max Power Dissipation: 125mW
R264 R265 = CMP-03412-047301-1: RES 0Ω 5.00% 0.1W 0603; Resistance: 0mR; Tolerance: 5%
TP62-TP64 TP81-TP83 = CMP-00028-00002-2: 0.6mm round
U12 U15 = FLXC2004G-N1

## Sheet BoardSupply.SchDoc
size custom portrait; SheetNumber: 13; SheetTotal: 22
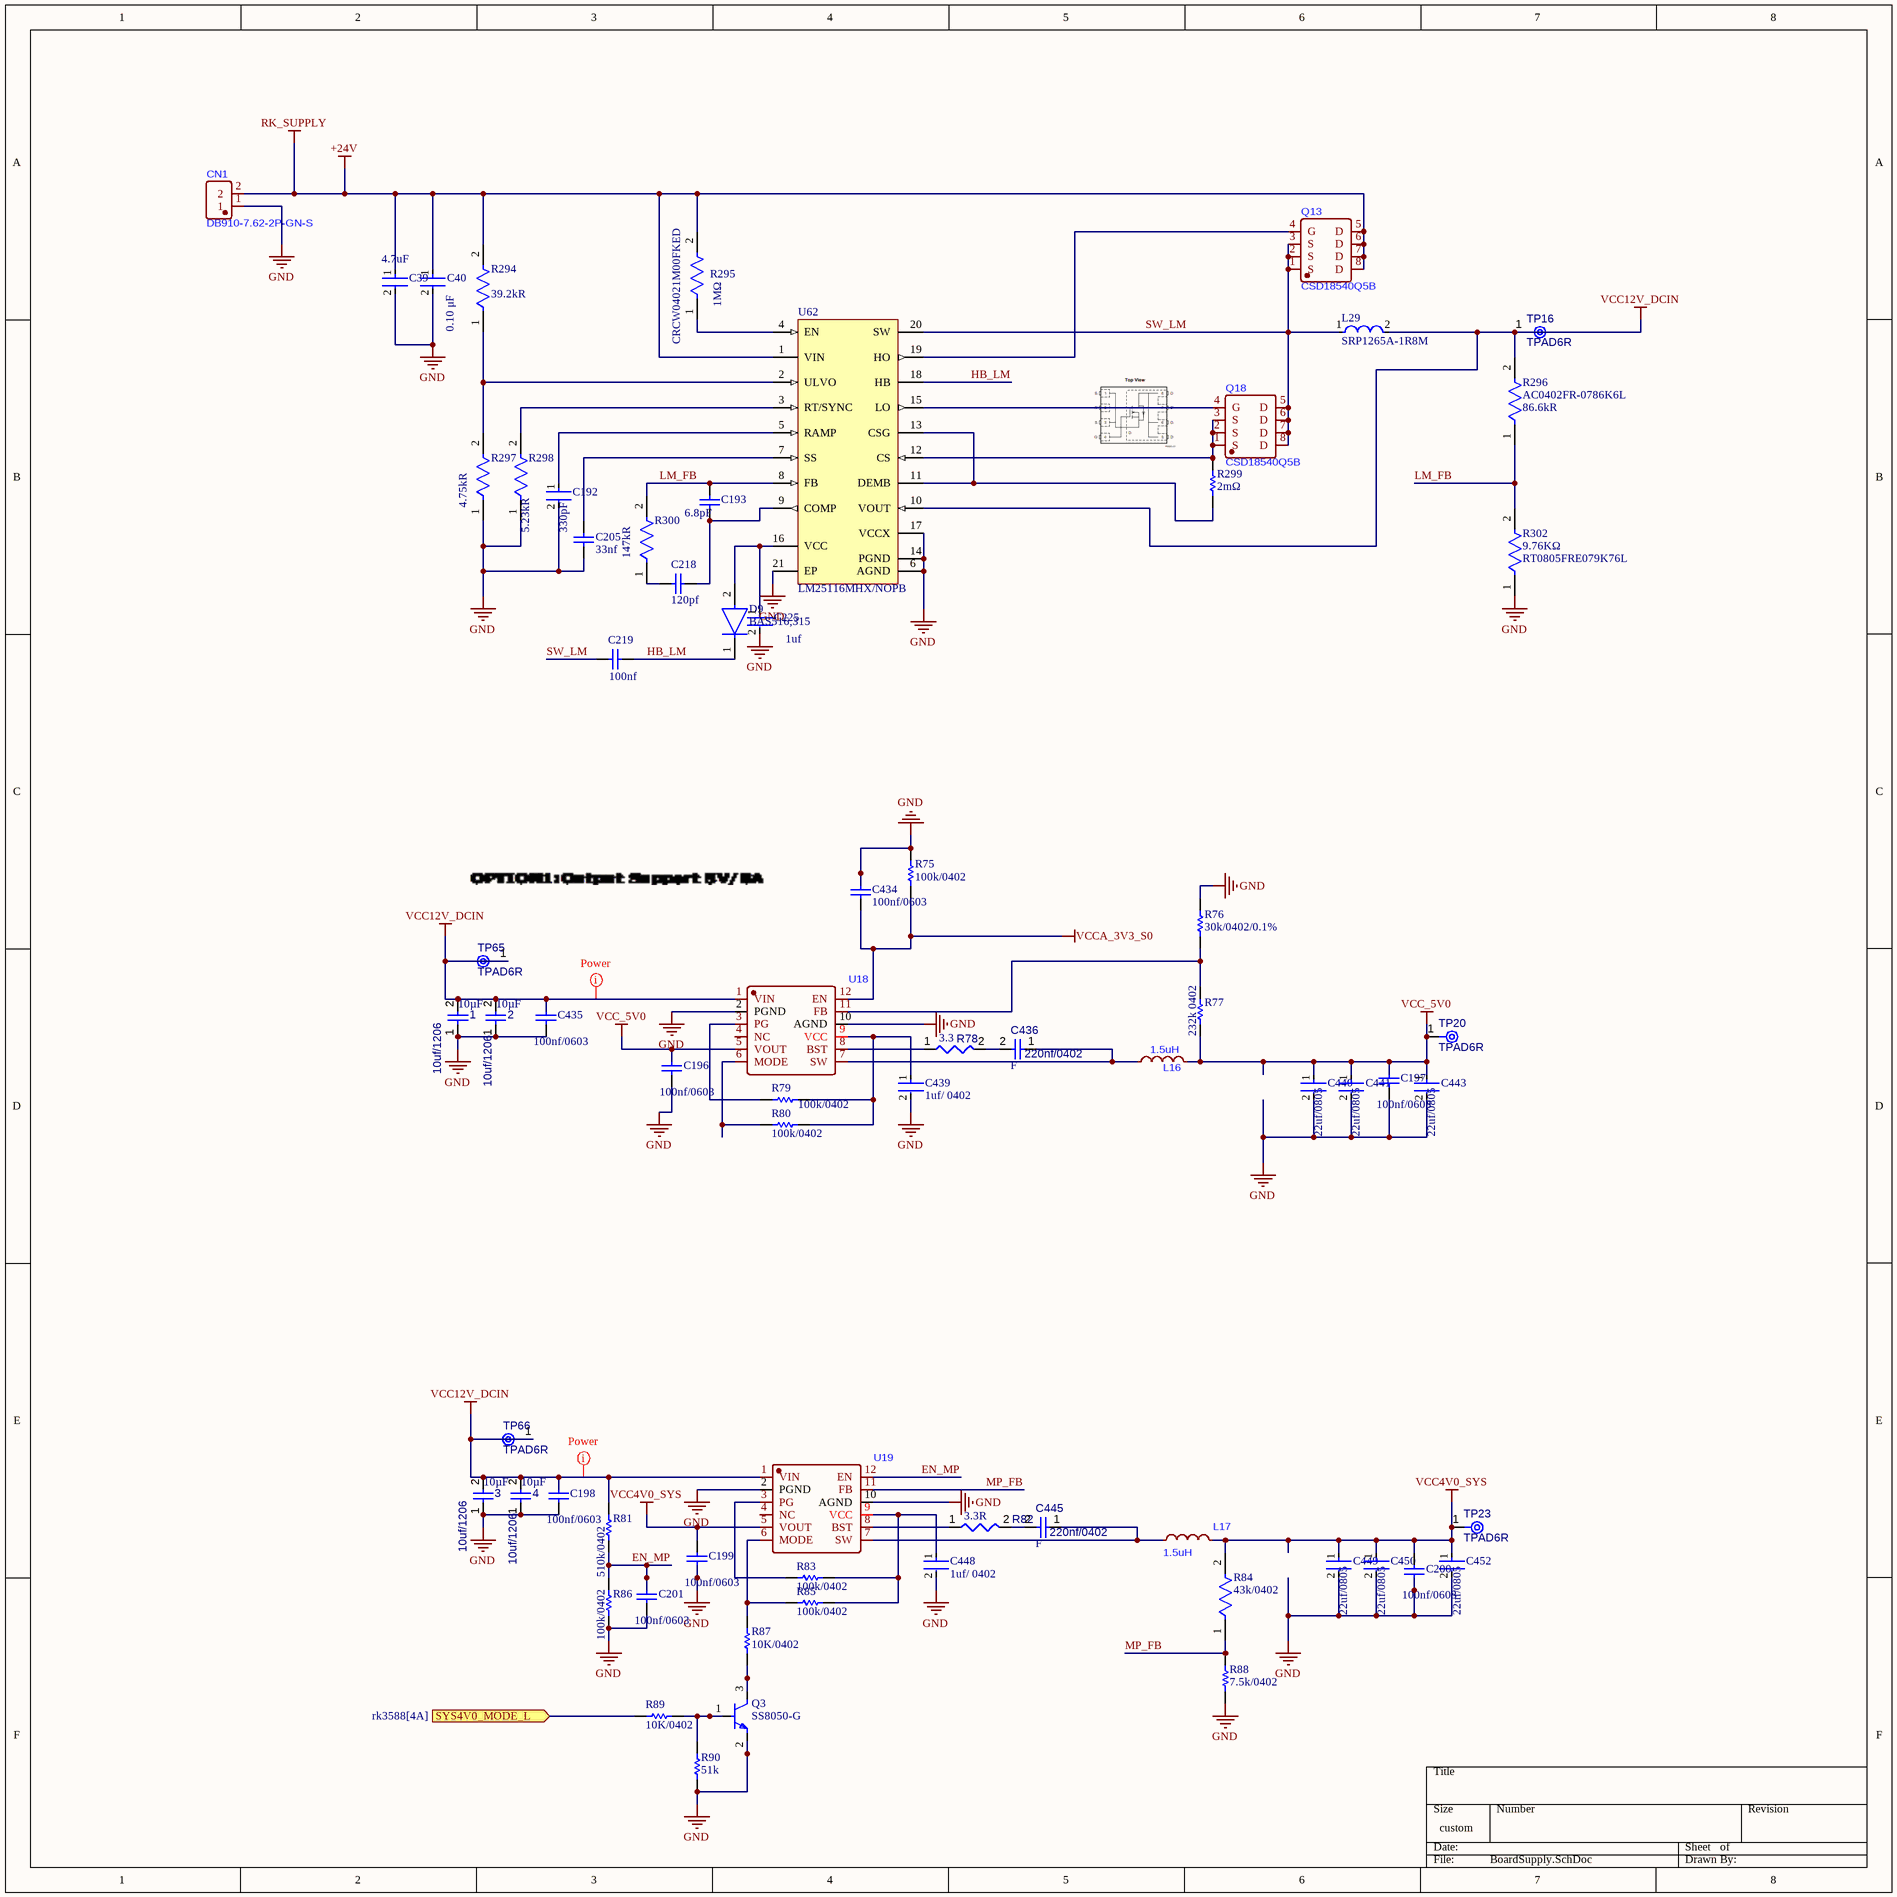
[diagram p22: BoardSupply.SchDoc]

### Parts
1  10uf/1206  value 10µF  [CAPC3216X180X50NL20T25]
2  10uf/1206  value 10µF  [CAPC3216X180X50NL20T25]
3  10uf/1206  value 10µF  [CAPC3216X180X50NL20T25]
4  10uf/1206  value 10µF  [CAPC3216X180X50NL20T25]
C39  Capacitance: 4.7uF  [FP-GRM31C-0_2-e0_3_0_8-IPC_C]  (hidden comment: GRM31CR71H475KA12L)
C40  value 0.10 μF  [FP-C0805C-DN-MFG]  (hidden comment: C0805C104M5RACTU)
C192  Capacitance: 330pF  [FP-0402-L_1_0_0_05-W_0_5-MFG]  (hidden comment: UMK105CG331JV-F)
C193  value 6.8pF  [CAPC1005X55X25NL05T10]  (hidden comment: GRM1555C1E6R8CA01D)
C196  100nf/0603  [CAPC1608X92X38ML15T08]
C197  100nf/0603  [CAPC1608X92X38ML15T08]
C198  100nf/0603  [CAPC1608X92X38ML15T08]
C199  100nf/0603  [CAPC1608X92X38ML15T08]
C200  100nf/0603  [CAPC1608X92X38ML15T08]
C201  100nf/0603  [CAPC1608X92X38ML15T08]
C205  33nf  [CAPC2013X145X48NL20T23]
C218  120pf  [CAPC1005X55X30ML05T10]
C219  value 100nf  [CAPC2013X140X50ML20T25]  (hidden comment: 08055D104KAT2A)
C225  value 1uf  [FP-GRM155-0_1-MFG]  (hidden comment: GRM155R61H105KE05D)
C434  100nf/0603  [CAPC1608X92X38ML15T08]
C435  100nf/0603  [CAPC1608X92X38ML15T08]
C436  220nf/0402  value F  [CAPC0402(1005)60_L]
C439  1uf/ 0402  [FP-GRM15-0_1-MFG]
C440  22uf/0805  [FP-GRM21B-0_2-e0_2_0_7-IPC_B]
C441  22uf/0805  [FP-GRM21B-0_2-e0_2_0_7-IPC_B]
C443  22uf/0805  [FP-GRM21B-0_2-e0_2_0_7-IPC_B]
C445  220nf/0402  value F  [CAPC0402(1005)60_L]
C448  1uf/ 0402  [FP-GRM15-0_1-MFG]
C449  22uf/0805  [FP-GRM21B-0_2-e0_2_0_7-IPC_B]
C450  22uf/0805  [FP-GRM21B-0_2-e0_2_0_7-IPC_B]
C452  22uf/0805  [FP-GRM21B-0_2-e0_2_0_7-IPC_B]
CN1  DB910-7.62-2P-GN-S  [CONN-TH_2P-P7.62_DB910-7.62-2P]
D9  BAS516,315  [FP-SOD523-MFG]
L16  1.5uH  [IND-SMD_L7.1-W6.6]
L17  1.5uH  [IND-SMD_L7.1-W6.6]
L29  SRP1265A-1R8M  [FP-SRP1265A-MFG]
Q3  SS8050-G  [FP-SS8050-G-MFG]
Q13  CSD18540Q5B  [VSON-CLIP-8_L5.0-W6.0-P1.27-BL]
Q18  CSD18540Q5B  [VSON-CLIP-8_L5.0-W6.0-P1.27-BL]
R75  100k/0402  [RESC1005X40X25NL05T10]
R76  30k/0402/0.1%  [RESC1005X35X20ML05T10]
R77  232k 0402  [RESC1005X40X25ML05T05]
R78  value 3.3  [RESC0402(1005)_L]  (hidden comment: 3D3R2J)
R79  100k/0402  [RESC1005X40X25NL05T10]
R80  100k/0402  [RESC1005X40X25NL05T10]
R81  510k/0402  [RESC1005X40X25NL05T10]
R82  value 3.3R  [RESC0402(1005)_L]  (hidden comment: 3D3R2J)
R83  100k/0402  [RESC1005X40X25NL05T10]
R84  43k/0402  [FP-AC0402-MFG]
R85  100k/0402  [RESC1005X40X25NL05T10]
R86  100k/0402  [RESC1005X40X25NL05T10]
R87  10K/0402  [RESC1005X40X25LL05T10]
R88  7.5k/0402  [RESC1005X40X25LL05T10]
R89  10K/0402  [RESC1005X40X25LL05T10]
R90  value 51k  [RESC1005X40X25ML05T10]  (hidden comment: Resistor 51k +/-5% 0402 63 mW)
R294  Resistance: 39.2kR  [FP-CRCW0805-e3-IPC_C]  (hidden comment: CRCW080539K2FKEA)
R295  CRCW04021M00FKED  [CRCW0402-e3_MFG]
R296  AC0402FR-0786K6L  Resistance: 86.6kR  [FP-AC0402-IPC_B]
R297  Resistance: 4.75kR  [FP-RNCP0805-IPC_A]  (hidden comment: RNCP0805FTD4K75)
R298  Resistance: 5.23kR  [FP-CRCW0402-e3-IPC_C]  (hidden comment: CRCW04025K23FKED)
R299  value 2mΩ  [RESC3116X70X50ML13T20]  (hidden comment: CSNL1206FT2L00)
R300  Resistance: 147kR  [FP-CRCW0402-e3-IPC_A]  (hidden comment: CRCW0402147KFKED)
R302  RT0805FRE079K76L  value 9.76KΩ  [FP-RT0805-MFG]
TP16  TPAD6R  [TP06R]  (no BOM)
TP20  TPAD6R  [TP06R]  (no BOM)
TP23  TPAD6R  [TP06R]  (no BOM)
TP65  TPAD6R  [TP06R]  (no BOM)
TP66  TPAD6R  [TP06R]  (no BOM)
U18  (no value)  [QFN-12_L3.0-W2.0-P0.5-TL_NB680]
U19  (no value)  [QFN-12_L3.0-W2.0-P0.5-TL_NB680]
U62  LM25116MHX/NOPB  [PWP0020A_N]

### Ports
SYS4V0_MODE_L (in, see rk3588[4A])

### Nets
+24V: C39.1 C40.1 CN1.2 Q13.5(D) Q13.6(D) Q13.7(D) Q13.8(D) R294.2 R295.2 U62.1(VIN)  [also labelled RK_SUPPLY]
GND: 1.1 2.1 3.1 4.1 C39.2 C40.2 C192.2 C196.1 C197.1 C198.1 C199.1 C200.1 C201.1 C205.1 C225.2 C434.2 C435.1 C439.2 C440.2 C441.2 C443.2 C448.2 C449.2 C450.2 C452.2 CN1.1 Q3.2(E) R75.1 R76.2 R86.1 R88.1 R90.1 R297.1 R298.1 R302.1 U18.2(PGND) U18.10(AGND) U19.2(PGND) U19.10(AGND) U62.6(AGND) U62.14(PGND) U62.17(VCCX) U62.21(EP)
VCC4V0_SYS: C199.2 C200.2 C449.1 C450.1 C452.1 L17.2 R84.2 TP23.1(TP) U19.5(VOUT)  [project net VCC1]
VCC12V_DCIN: 1.2 2.2 3.2 4.2 C198.2 C435.2 L29.2 R81.2 R296.2 TP16.1(TP) TP65.1(TP) TP66.1(TP) U18.1(VIN) U19.1(VIN) U62.10(VOUT)  [project net 12V]
VCC_5V0: C196.2 C197.2 C440.1 C441.1 C443.1 L16.2 R77.1 TP20.1(TP) U18.5(VOUT)
VCCA_3V3_S0: C434.1 R75.2 U18.12(EN)  [project net PLDO4]
EN_MP: C201.2 R81.1 R86.2 U19.12(EN)
HB_LM: C219.2 D9.1(C) U62.18(HB)
LM_FB: C193.2 R296.1 R300.2 R302.2 U62.8(FB)
MP_FB: R84.1 R88.2 U19.11(FB)
SW_LM: C219.1 L29.1 Q13.1(S) Q13.2(S) Q13.3(S) Q18.5(D) Q18.6(D) Q18.7(D) Q18.8(D) U62.20(SW)
SYS4V0_MODE_L: R89.2 ; port SYS4V0_MODE_L
NetC192_1: C192.1 U62.5(RAMP)
NetC193_1: C193.1 C218.1 U62.9(COMP)
NetC205_2: C205.2 U62.7(SS)
NetC218_2: C218.2 R300.1
NetC225_1: C225.1 D9.2(A) U62.16(VCC)
NetC436_1: C436.1 L16.1 U18.7(SW)
NetC436_2: C436.2 R78.2
NetC439_1: C439.1 R79.1 R80.1 U18.9(VCC)
NetC445_1: C445.1 L17.1 U19.7(SW)
NetC445_2: C445.2 R82.2
NetC448_1: C448.1 R83.1 R85.1 U19.9(VCC)
NetQ3_1: Q3.1(B) R89.1 R90.2
NetQ3_3: Q3.3(C) R87.1
NetQ13_4: Q13.4(G) U62.19(HO)
NetQ18_1: Q18.1(S) Q18.2(S) Q18.3(S) R299.2 U62.12(CS)
NetQ18_4: Q18.4(G) U62.15(LO)
NetR76_1: R76.1 R77.2 U18.11(FB)
NetR78_1: R78.1 U18.8(BST)
NetR79_2: R79.2 U18.3(PG)
NetR80_2: R80.2 U18.6(MODE)
NetR82_1: R82.1 U19.8(BST)
NetR83_2: R83.2 U19.3(PG)
NetR85_2: R85.2 R87.2 U19.6(MODE)
NetR294_1: R294.1 R297.2 U62.2(ULVO)
NetR295_1: R295.1 U62.4(EN)
NetR298_2: R298.2 U62.3(RT/SYNC)
NetR299_1: R299.1 U62.11(DEMB) U62.13(CSG)

Not connected (* = marked no-connect by the designer): U18 4(NC); U19 4(NC)

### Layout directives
net class Power: 12V

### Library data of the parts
1-4 = CMP-001-00016-6: 10uF 50V X5R ±10% 1206 Multilayer Ceramic Capacitors MLCC - SMD/SMT ROHS; Voltage Rating: 50; MN: CL31A106KBHNNNE
C39 = CMP-1037-04923-3: Chip Multilayer Ceramic Capacitors for General Purpose, 1206, 4.7uF, X7R, 15%, 10%, 50V
C40 = CMP-1036-04423-3: CAP CER 0.1UF 50V X7R 0805; Manufacturer: KEMET; Tolerance: 0.2; Temperature Coefficient: 30ppm/°C; Material: Ceramic
C192 = CMP-14477-001428-2: Voltage Rating: 50V; Tolerance: 5%; Dielectric: C0G
C193 = CMP-2008-04219-1: Manufacturer: Murata
C196-C201 C434 C435 = CMP-2006-01140-1: Part Number: VJ0603Y104MXXAC; Manufacturer: Vitramon
C205 = CMP-2007-01741-1: VJ-0805Y333KXBMT; Manufacturer: Vitramon
C218 = CMP-2008-03481-1: C0402C121G5GACTU; Manufacturer: Kemet
C219 = CMP-2007-04689-1: Manufacturer: AVX Interconnect / Elco
C225 = CMP-06035-026840-2: CERAMIC CAP, MLCC 1UF 50VDC X5R
C436 C445 = CMP-001-00057-3: Chip Capacitor, 220nF +/-20%, 10V, 0402, Thickness 0.6 mm; Tolerance: 10%; MN: CL05A224KA5NNNC
C439 C448 = CMP-2008-04556-2: CAP CER 1UF 10V X5R 0402; Manufacturer Part Number: GRM155R61A105KE15D; Manufacturer: Murata; Material: Ceramic; Tolerance: 10%; Temperature Coefficient: 15%
C440 C441 C443 C449 C450 C452 = CMP-2007-03222-3: 22uF 25V X5R ±20% 0805 Multilayer Ceramic Capacitors MLCC - SMD/SMT ROHS
CN1 = DB910-7.62-2P: -40℃~+105℃ 0.5~4 1 10~26 1x2P 2 21.8mm 2P 300V 30A 7.62mm Green M3 Through Hole Plugin,P=7.62mm Screw Terminal Blocks ROHS
D9 = CMP-14399-000014-1: DIODE GEN PURP 100V 250MA SOD523
L16 L17 = SMMS0650-1R5M
L29 = CMP-07248-000022-1: FIXED IND 1.8UH 24A 4.0 MOHM SMD; Manufacturer: Bourns; Self Resonant Frequency: 30MHz; Automotive Grade: Grade 0; Series Resistance: 4mΩ; Tolerance: 20%; Shielding: true; Test Frequency: 100kHz; Core Material: Carbonyl Powder; Saturation Current: 40A; Q Factor: 20
Q3 = CMP-20235-000001-1: NPN TRANSISTOR 1.5A 40V SOT-23 R; Transition Frequency: 100MHz; Max Breakdown Voltage: 25V; Collector Emitter Voltage (VCEO): 400mV; Max Power Dissipation: 300mW
Q13 Q18 = CSD18540Q5B: -55℃~+175℃ 1 N-channel 1.9V 2.6mΩ 205A 20pF 3.8W 4.23nF 41nC@10V 60V 808pF N-Channel VSON-8(5x6) MOSFETs ROHS
R75 R79 R80 R83 R85 R86 = CMP-2002-07343-1: Part Number: RC0402FR-07100KL; Manufacturer: Yageo / Phycomp
R76 = CMP-2002-03447-1: Part Number: CPF0402B30KE1; Manufacturer: TE Connectivity / AMP
R77 = CMP-2002-08387-1: Part Number: CRCW0402232KFKED; Manufacturer: Vishay Dale
R78 R82 = CMP-009-00098-2: 3R3 0.063W 5% 0402 (1005 Metric)  SMD; Power: 63mW; MN: 0402WGJ033JTCE
R81 = CMP-2002-08016-1: Part Number: RC0402JR-07510KL; Manufacturer: Yageo
R84 = CMP-03412-011926-2: RES 43kΩ ±1% 0.063W 0402; Power Rating: 63mW; Temperature Coefficient: 100ppm/°C; Resistance: 43kR
R87 R89 = CMP-2002-07353-1: -55℃~+155℃ 10kΩ 50V 62.5mW Thick Film Resistor ±1% ±100ppm/℃ 0402 Chip Resistor - Surface Mount ROHS; Part Number: RC0402FR-0710KL; Manufacturer: Yageo / Phycomp
R88 = CMP-1011-00609-2: Part Number: RC0402FR-077K5L; Manufacturer: Yageo / Phycomp
R90 = CMP-009-00000-5: Chip Resistor, 51 KOhm, +/- 5%, 0.063 W, -55 to 155 degC, 0402 (1005 Metric); Power: 63mW; MN: RC0402JR-0751KL
R294 = CMP-2001-03865-2: RES Thick Film, 39.2kΩ, 1%, 0.125W, 100ppm/°C, 0805; Max Power Dissipation: 125mW; Voltage Rating (DC): 150V
R295 = CMP-2002-08314-3: 63mW Thick Film Resistors 75V ±1% ±100ppm/℃ 1MΩ 0402 Chip Resistor - Surface Mount ROHS; Voltage Rating: 50V; Temperature Coefficient: 100ppm/°C
R296 = CMP-03412-015018-2: RES 86.6kΩ ±1% 0.063W 0402; Voltage Rating: 50V; Power Rating: 62.5mW; Max Power Dissipation: 63mW; Temperature Coefficient: 100ppm/°C
R297 = CMP-26527-004936-1: 4.75kΩ ±1% 0.25W 0805 High Power Anti-Sulfur Thin Film Chip Resistor; Temperature Coefficient: 100ppm/°C; Max Power Dissipation: 250mW
R298 = CMP-2002-00118-4: RES Thick Film, 5.23kΩ, 1%, 0.063W, 100ppm/°C, 0402; Max Power Dissipation: 63mW; Working Voltage: 50V
R299 = CMP-009-00008-5: 1W 2mΩ Current Sense Resistor ±1% ±50ppm/℃ 1206 Current Sense Resistors / Shunt Resistors ROHS; Tolerance: 0.05%; Voltage Rating: 200V
R300 = CMP-2002-08205-3: RES Thick Film, 147kΩ, 1%, 0.063W, 100ppm/°C, 0402; Voltage Rating: 50V; Power Rating: 63mW
R302 = CMP-03412-004791-1: RES SMD 9.76K OHM 1% 1/8W 0805; Manufacturer: Yageo; Power Rating: 0.125W; Temperature Coefficient: 50 ppm/°C; Tolerance: 0.0001; Voltage Rating: 150V
TP16 TP20 TP23 TP65 TP66 = CMP-00028-00002-2: 0.6mm round
U18 U19 = MP8759GD-Z
U62 = CMP-0069-01417-3: Wide Range Synchronous Buck Controller, 20-pin TSSOP-EP, Pb-Free; Manufacturer: Texas Instruments; CompType: Switcher; PowerWise: Y; PackageTopMarking: NSUZXYTT*LM25116*MH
